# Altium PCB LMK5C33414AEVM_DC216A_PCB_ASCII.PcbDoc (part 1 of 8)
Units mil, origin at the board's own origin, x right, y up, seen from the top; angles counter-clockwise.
Board outline 7000 x 9161 mil, 8 copper layers (L1-Top Layer (GTL), L2-GND Plane (GP1), L3-Mid-Layer 2 (G1), L4-Mid-Layer 3 (G2), L5-Mid-Layer 4 (G3), L6-Mid-Layer 5 (G4), L7-Mid-Layer 6 (G5), L8-Bottom Layer (GBL)), stack 61.2 mil thick; 523 components, 286 nets, 1391 pads, 2227 vias.
Unrouted connection lines stored in the file: 56.
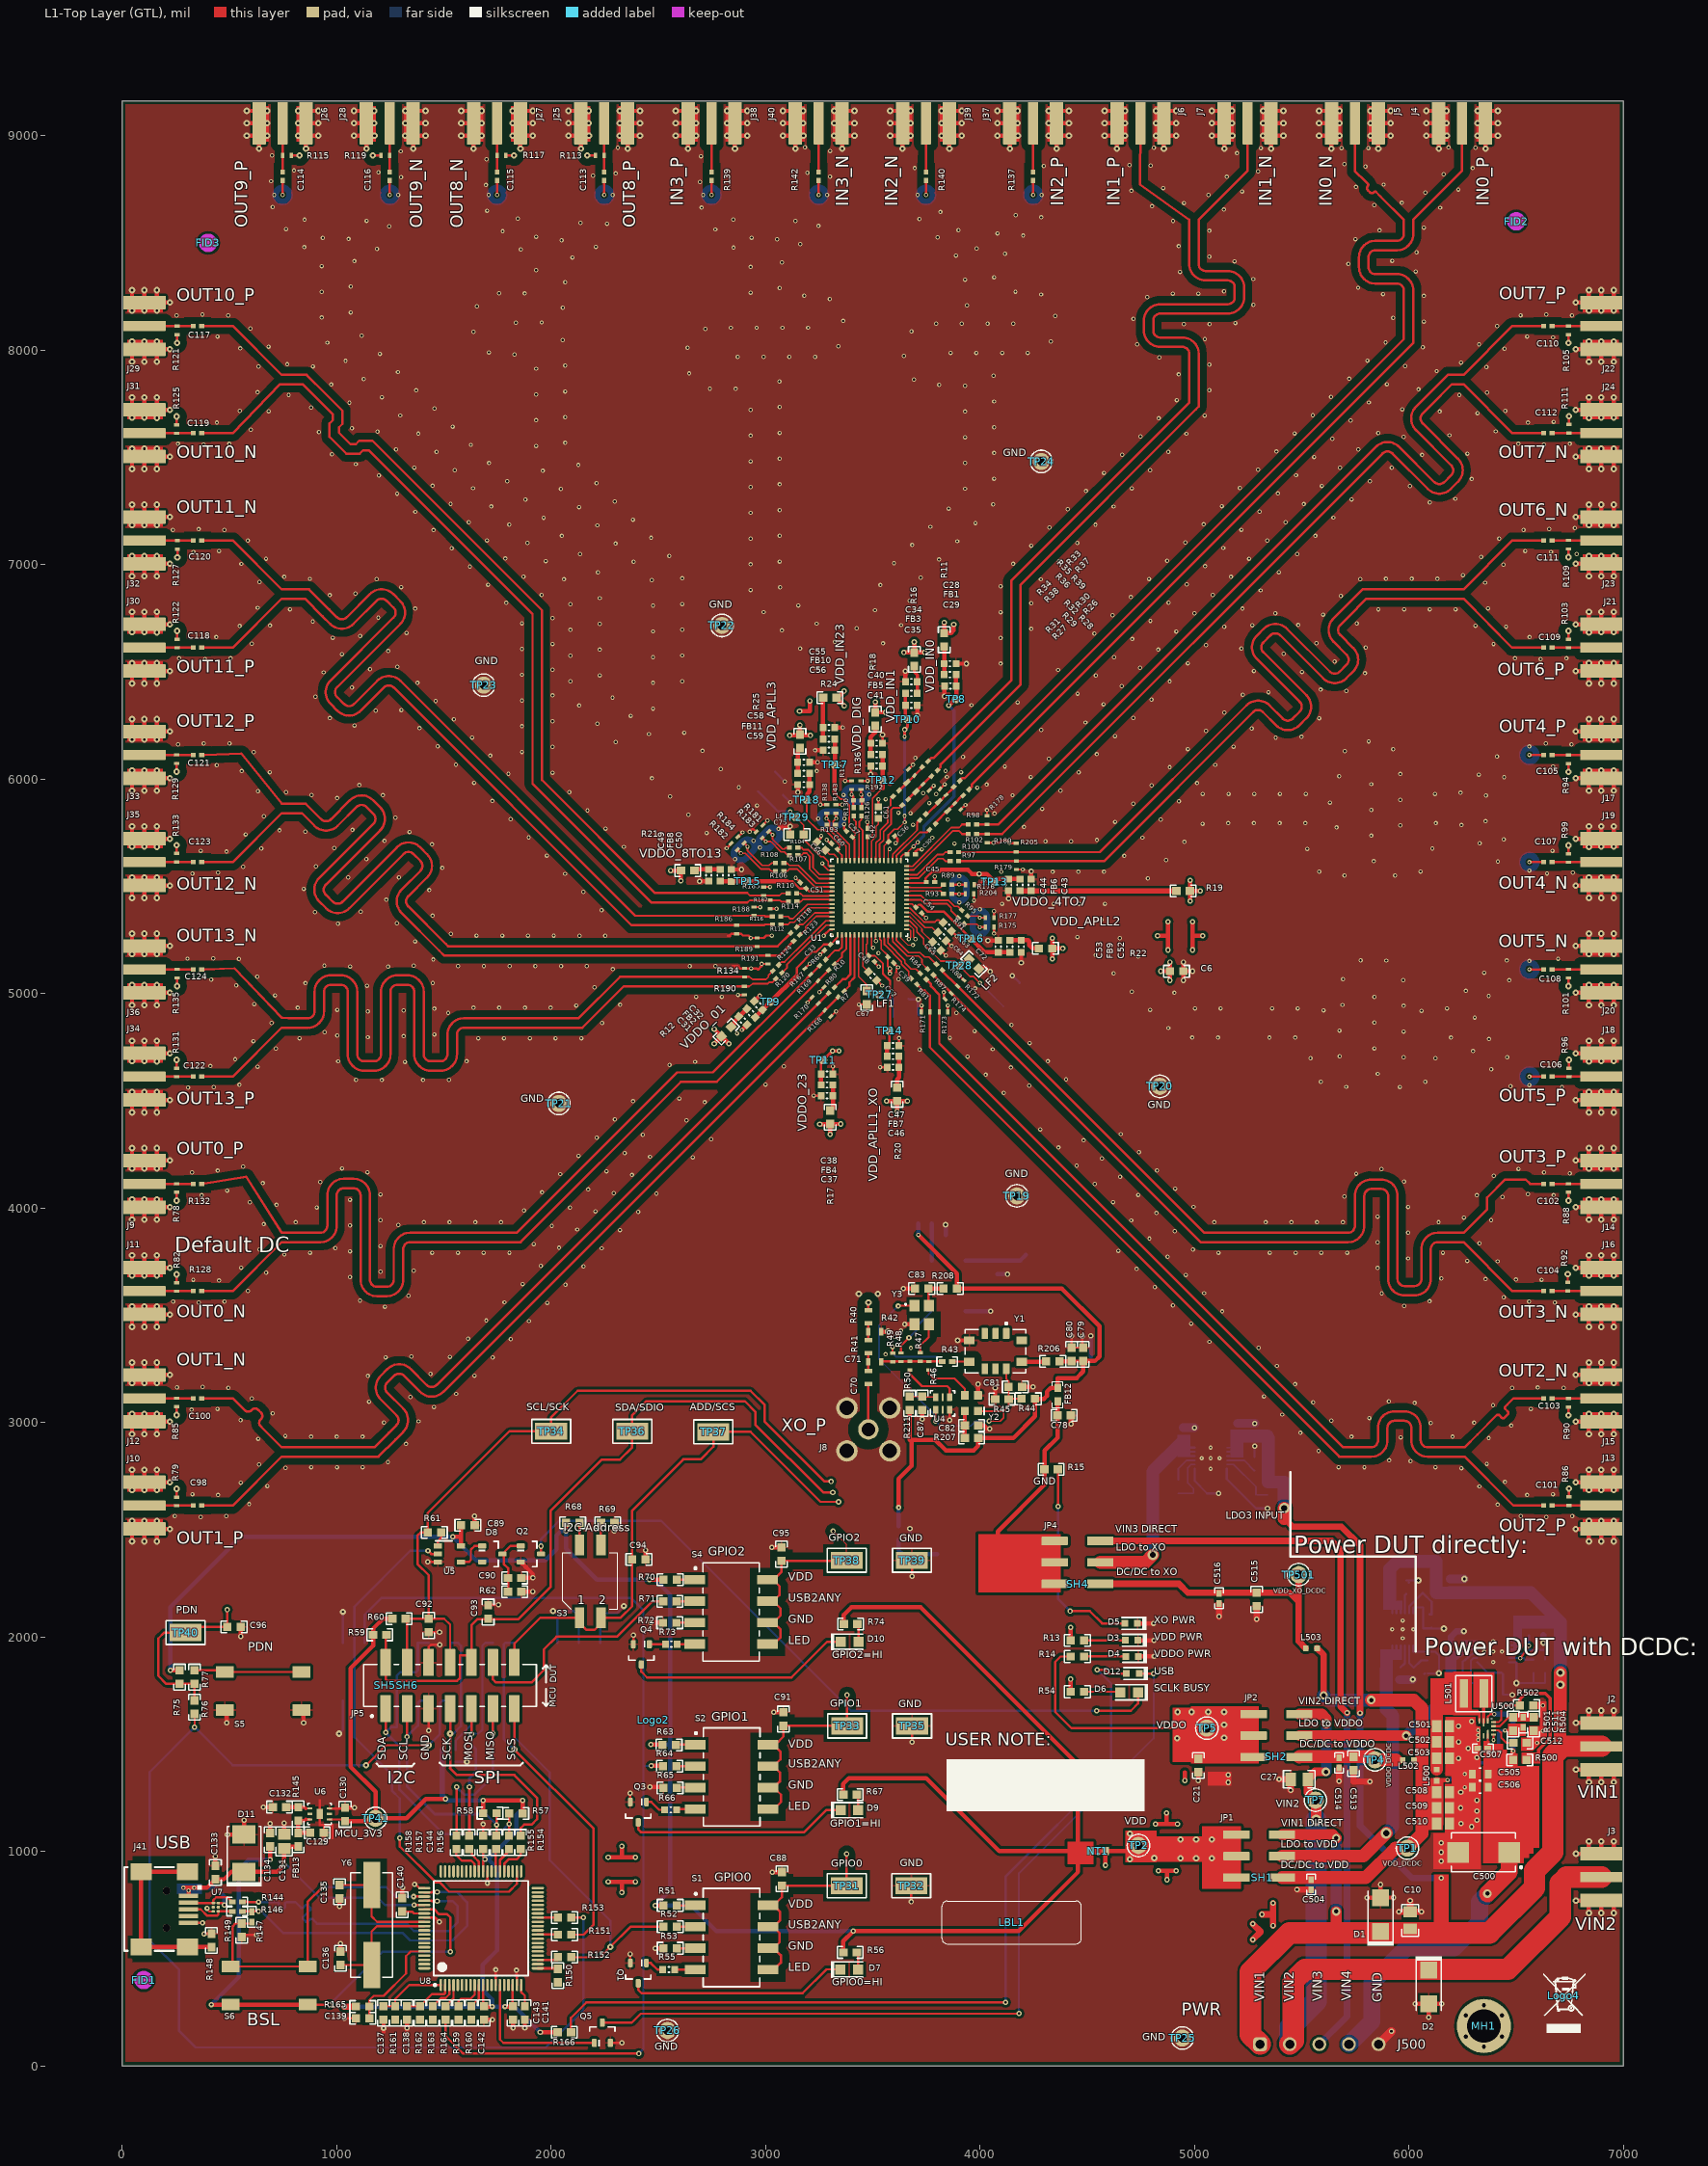
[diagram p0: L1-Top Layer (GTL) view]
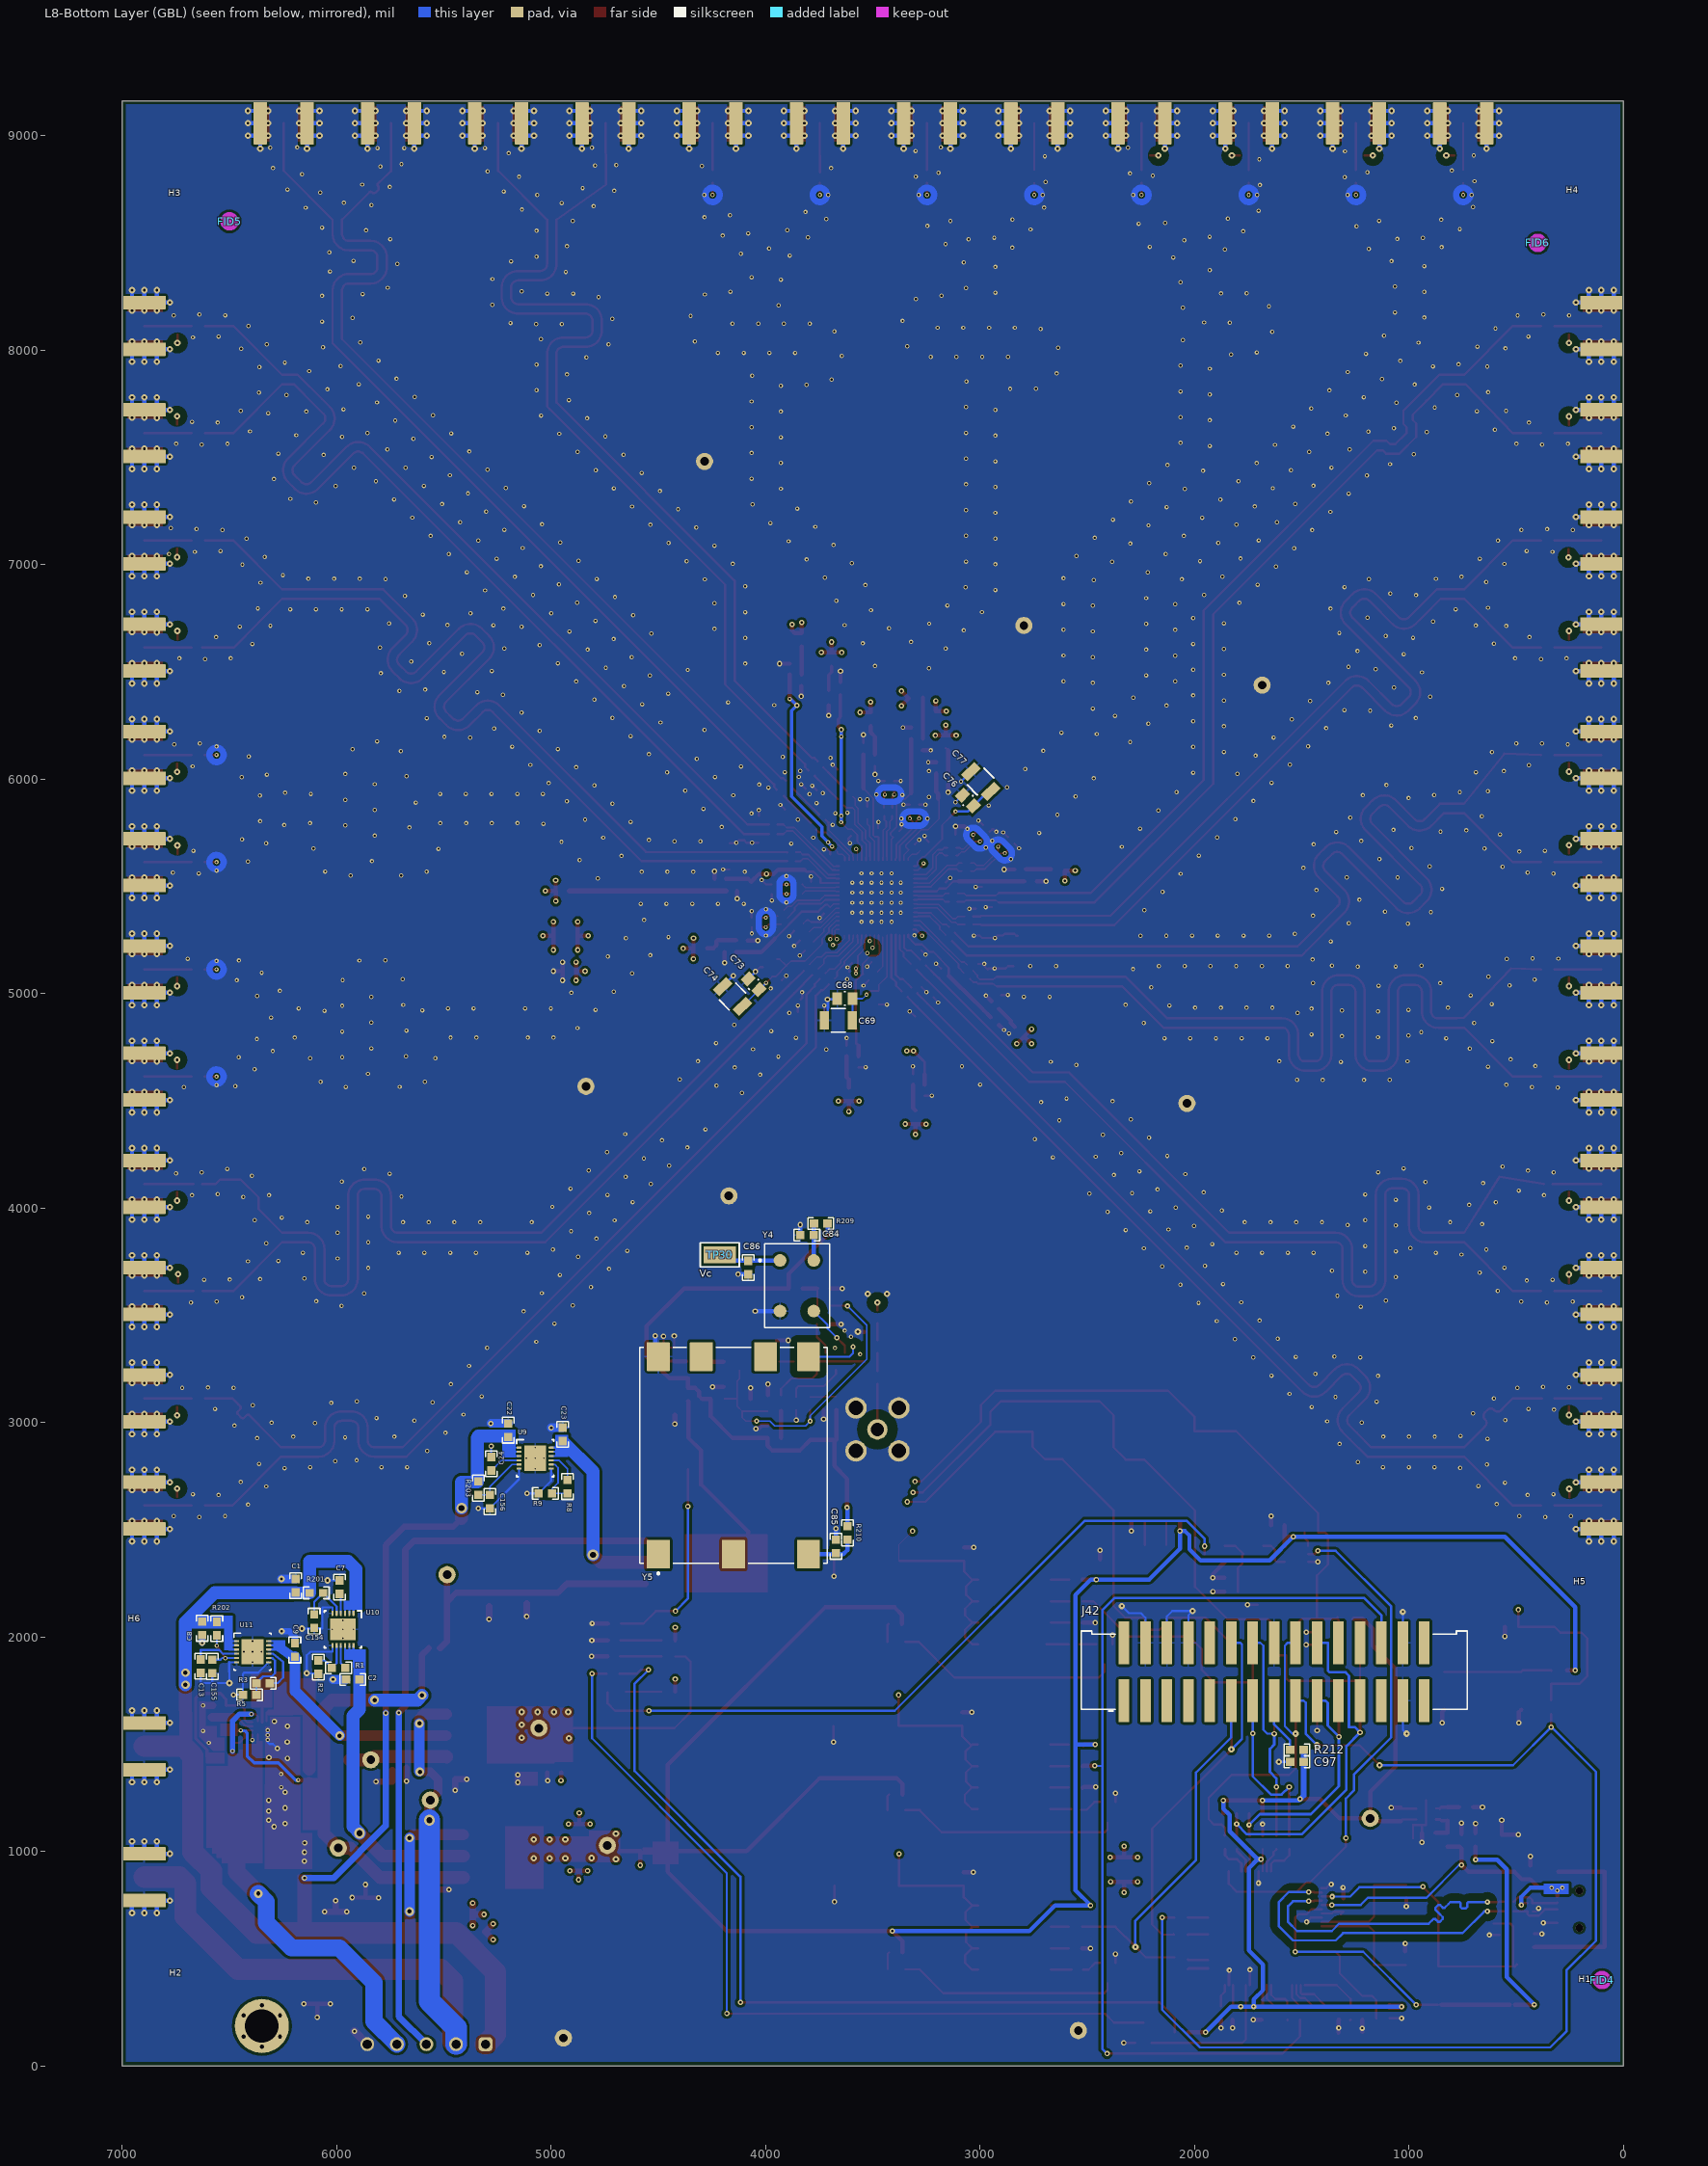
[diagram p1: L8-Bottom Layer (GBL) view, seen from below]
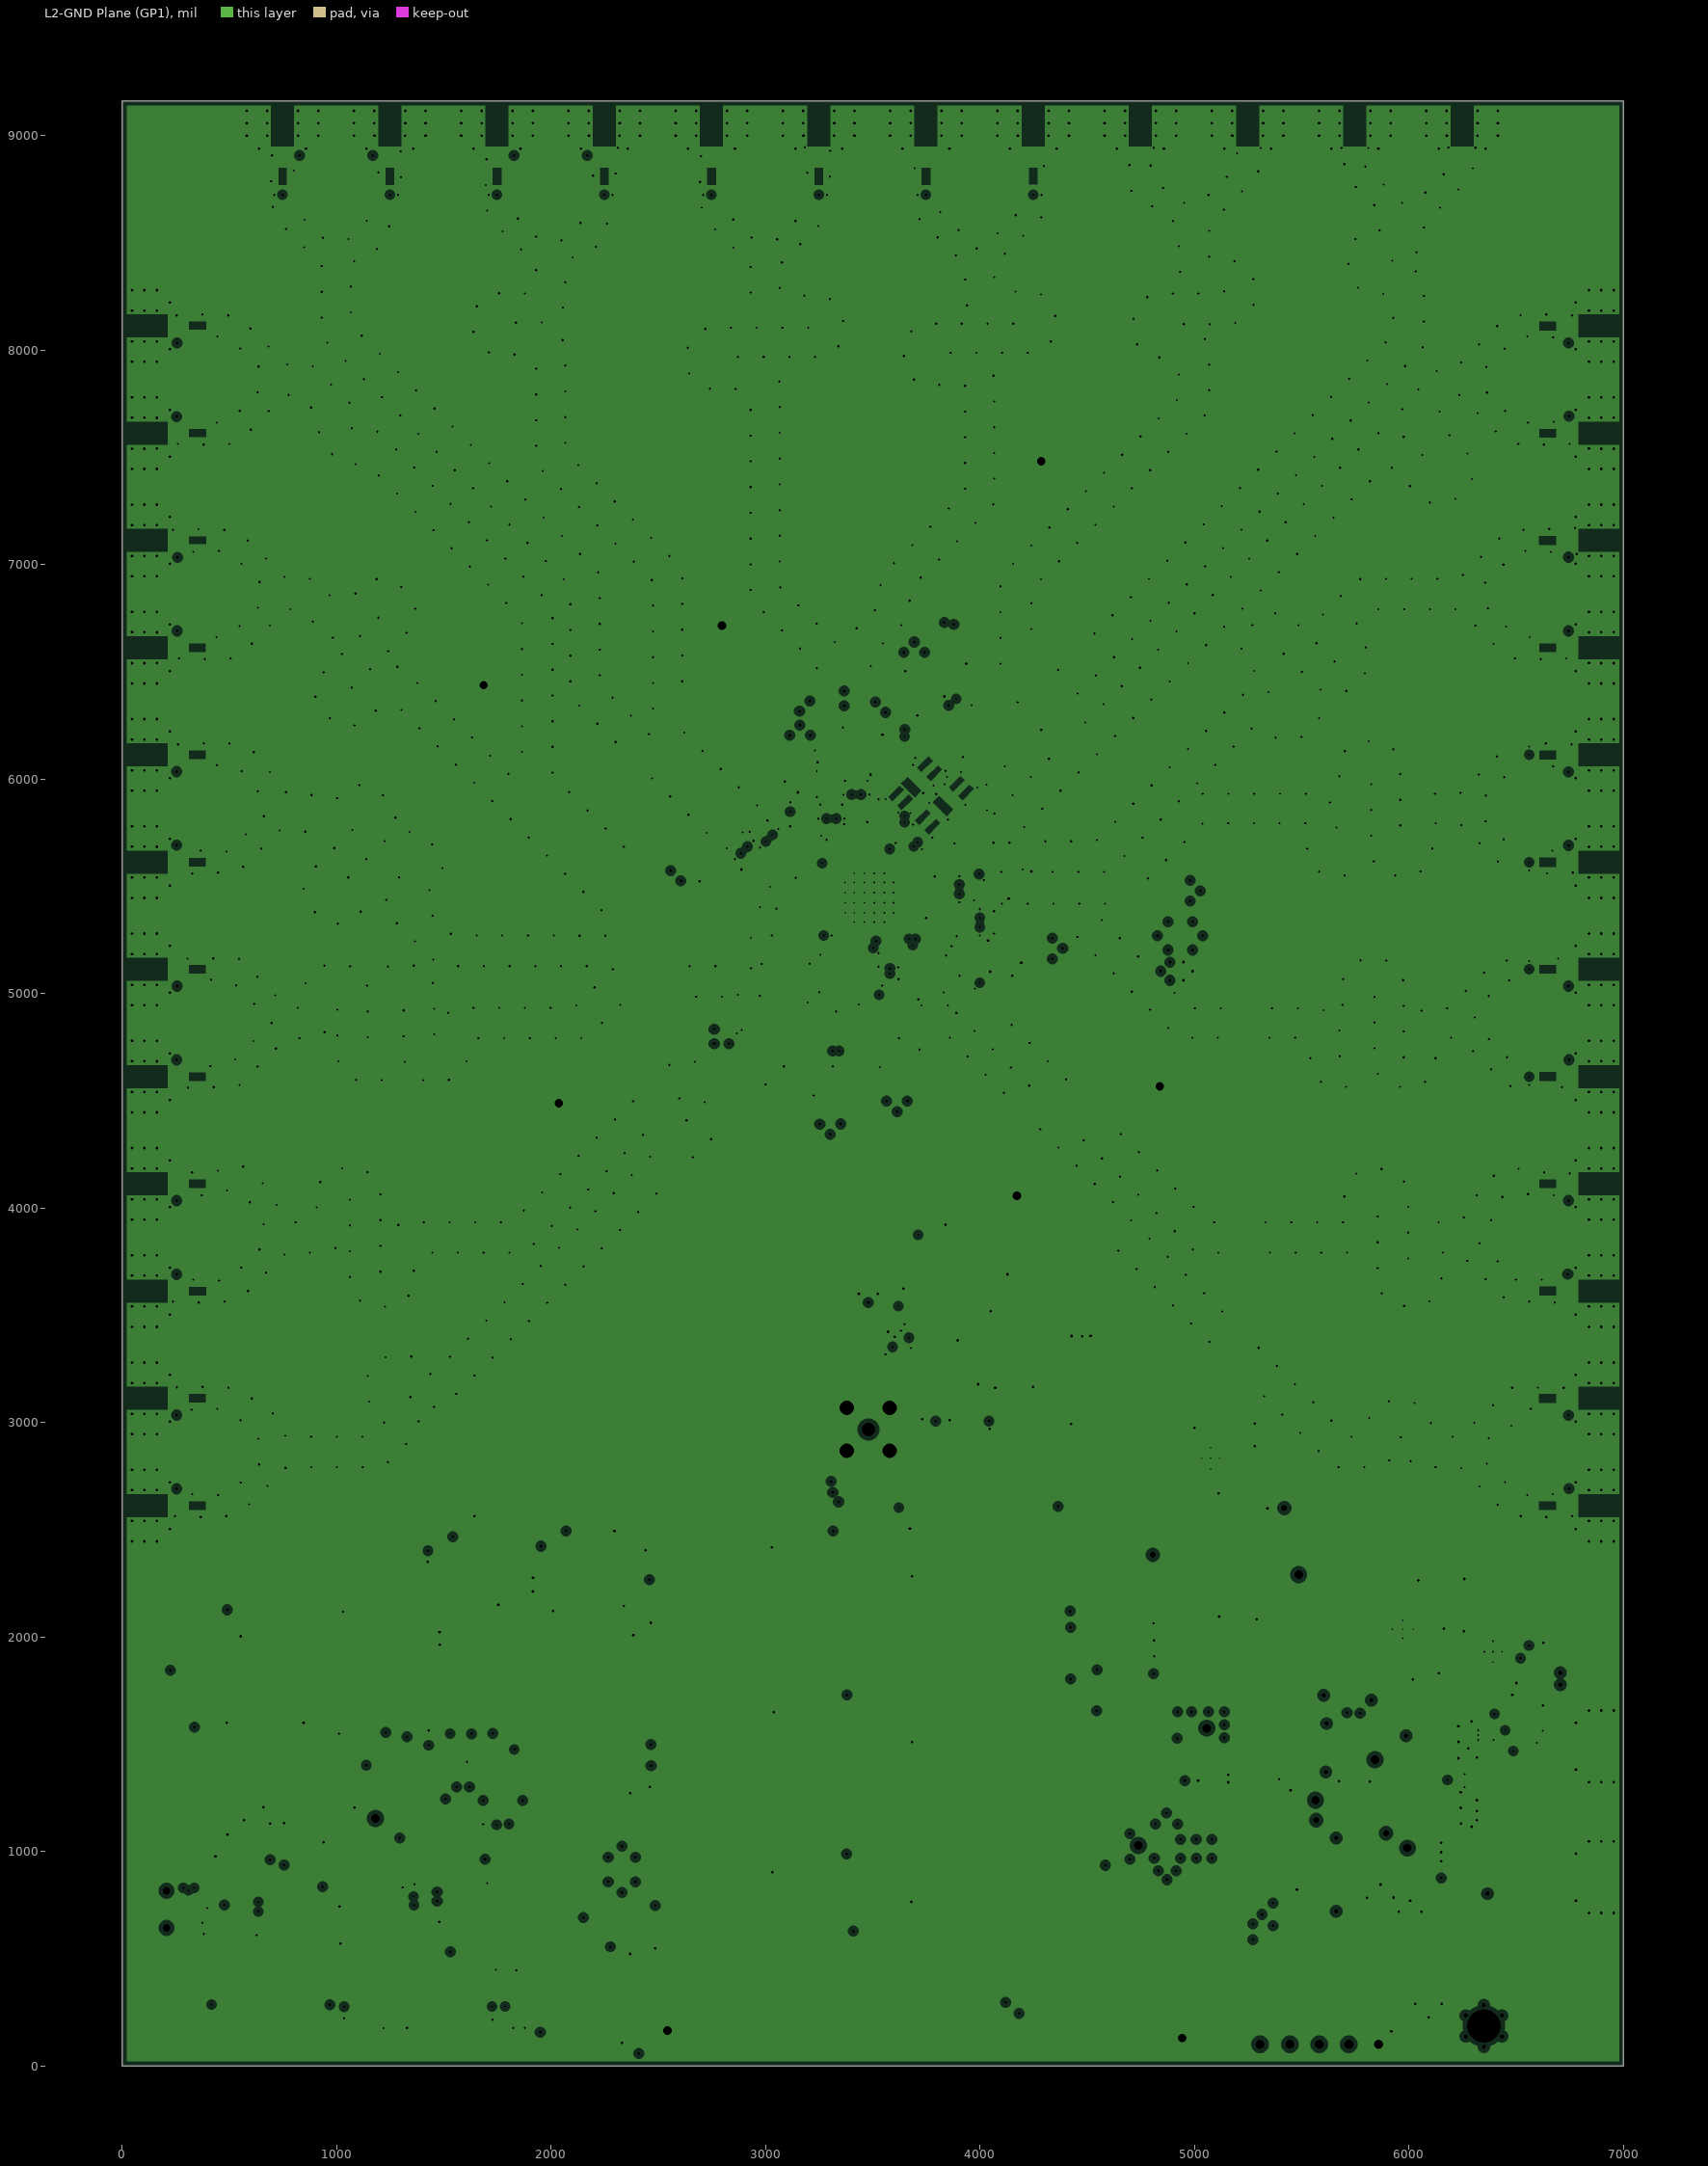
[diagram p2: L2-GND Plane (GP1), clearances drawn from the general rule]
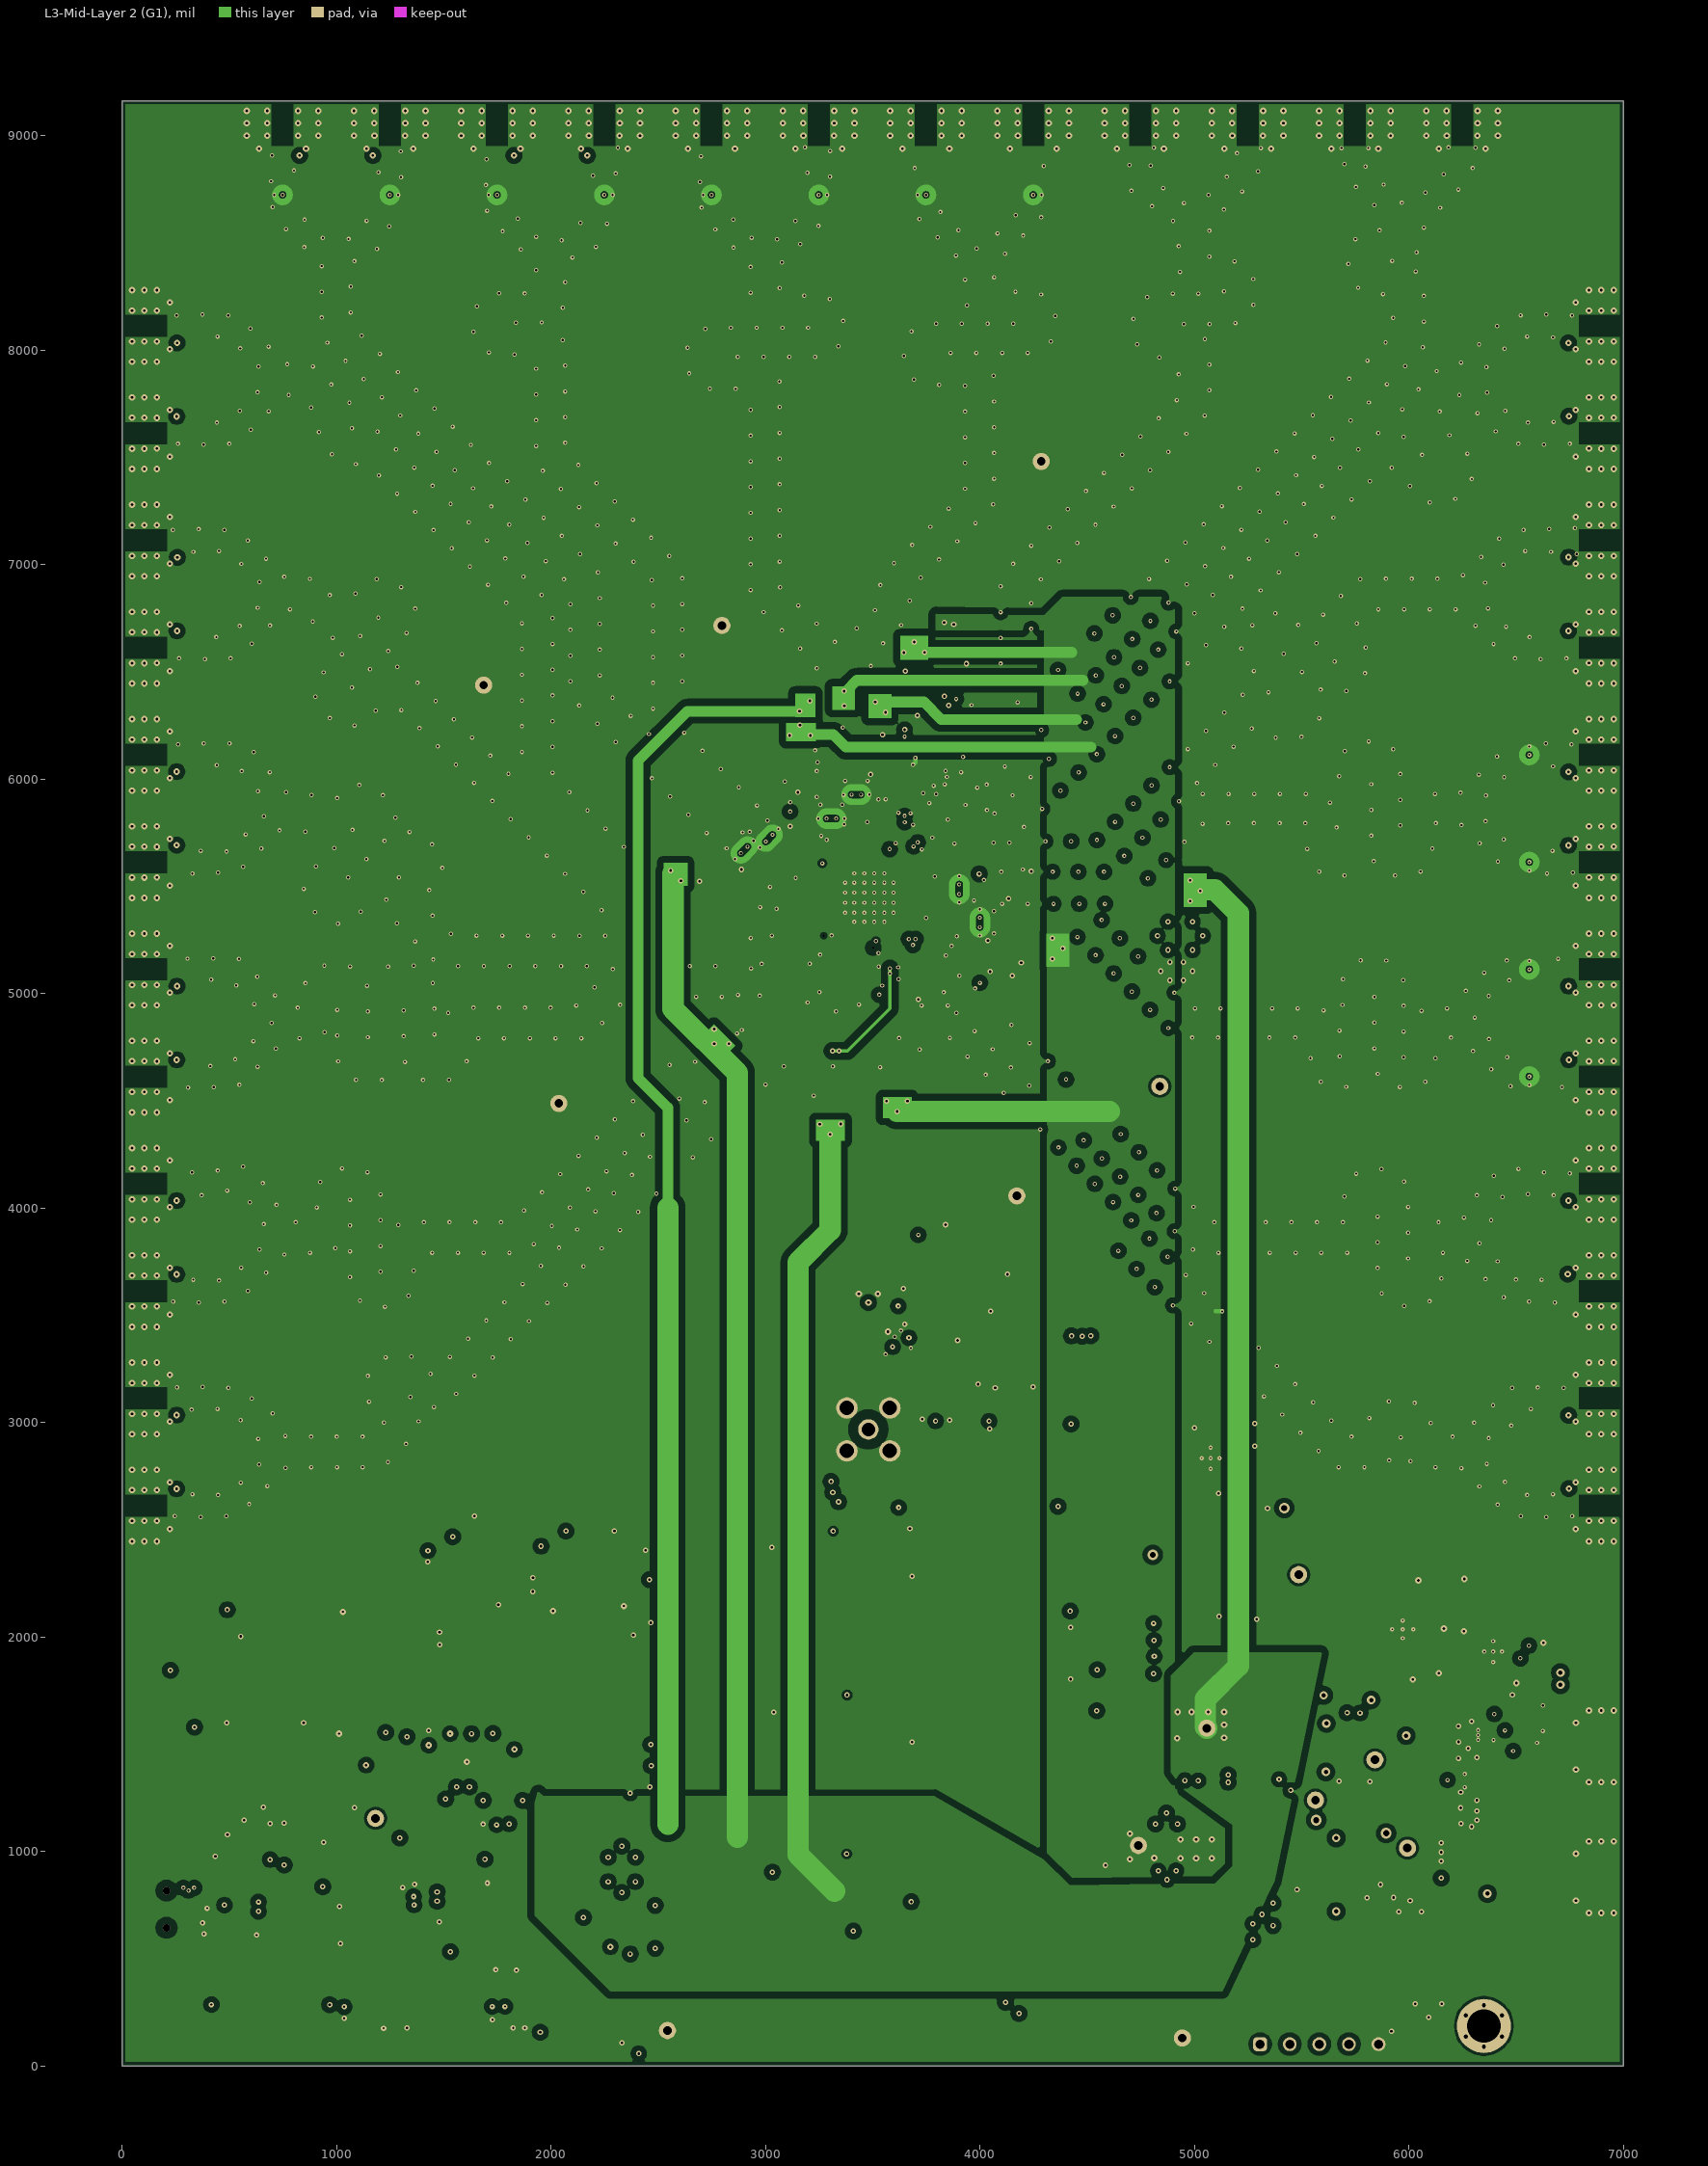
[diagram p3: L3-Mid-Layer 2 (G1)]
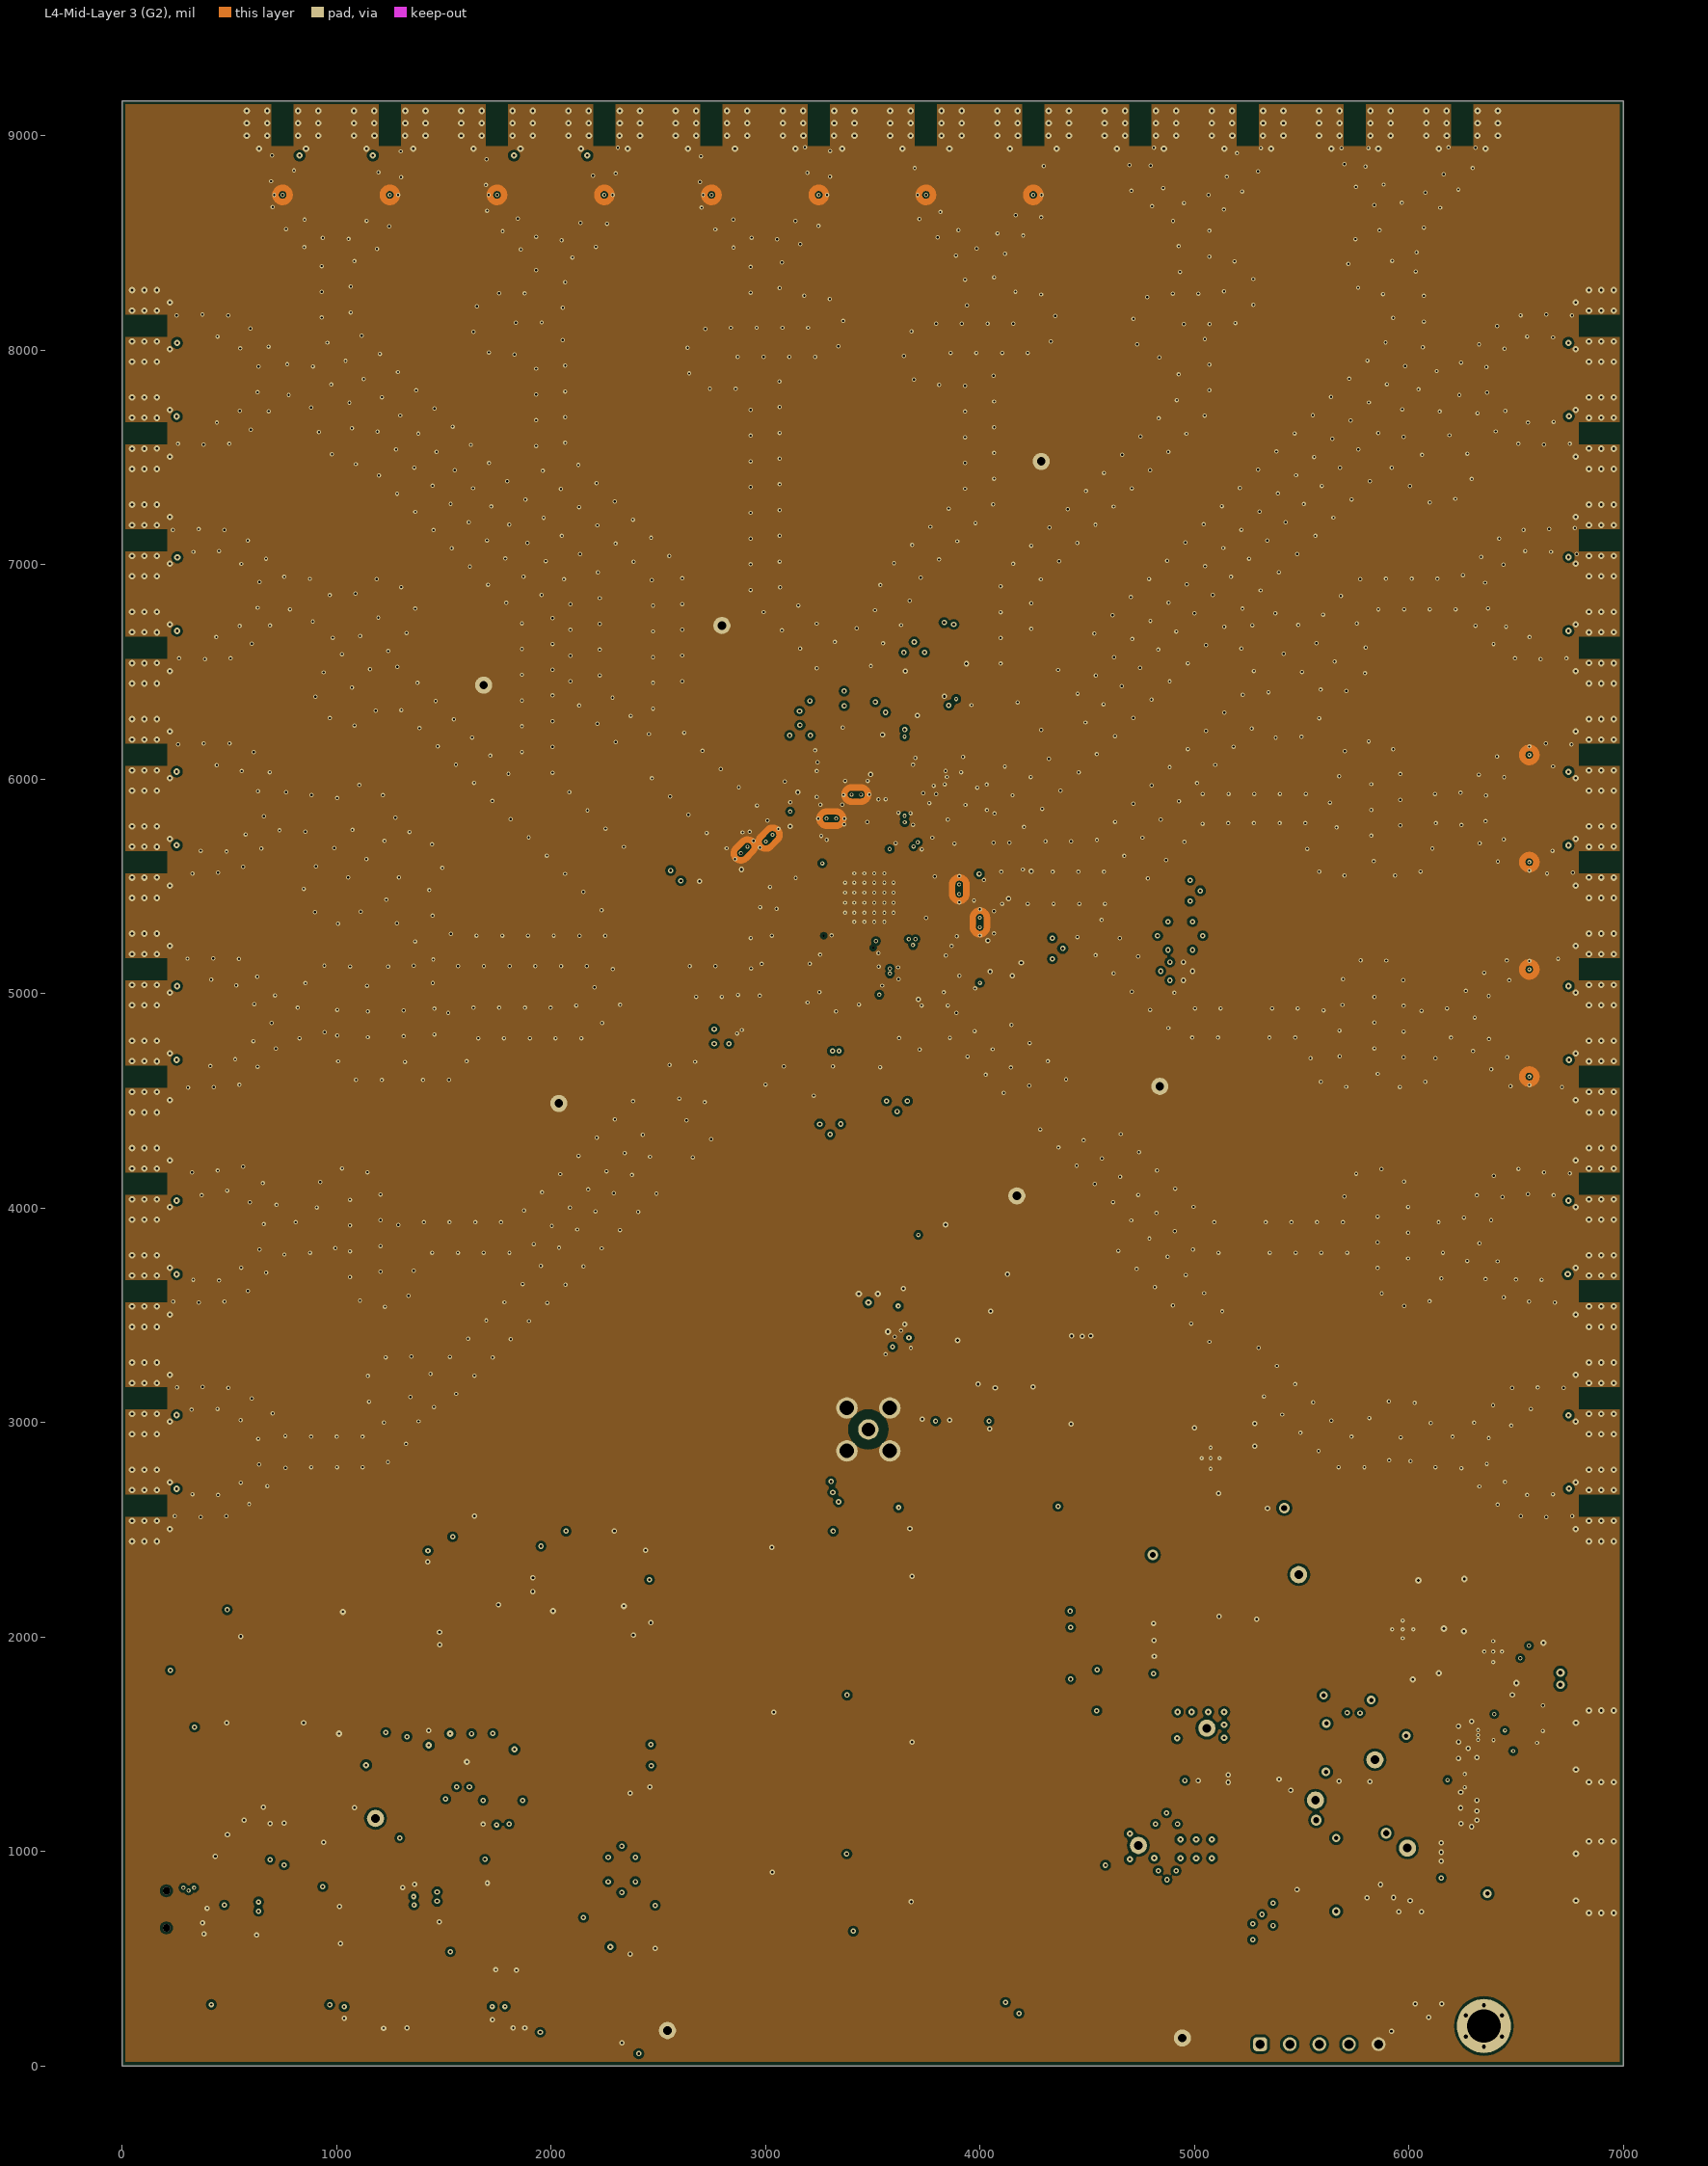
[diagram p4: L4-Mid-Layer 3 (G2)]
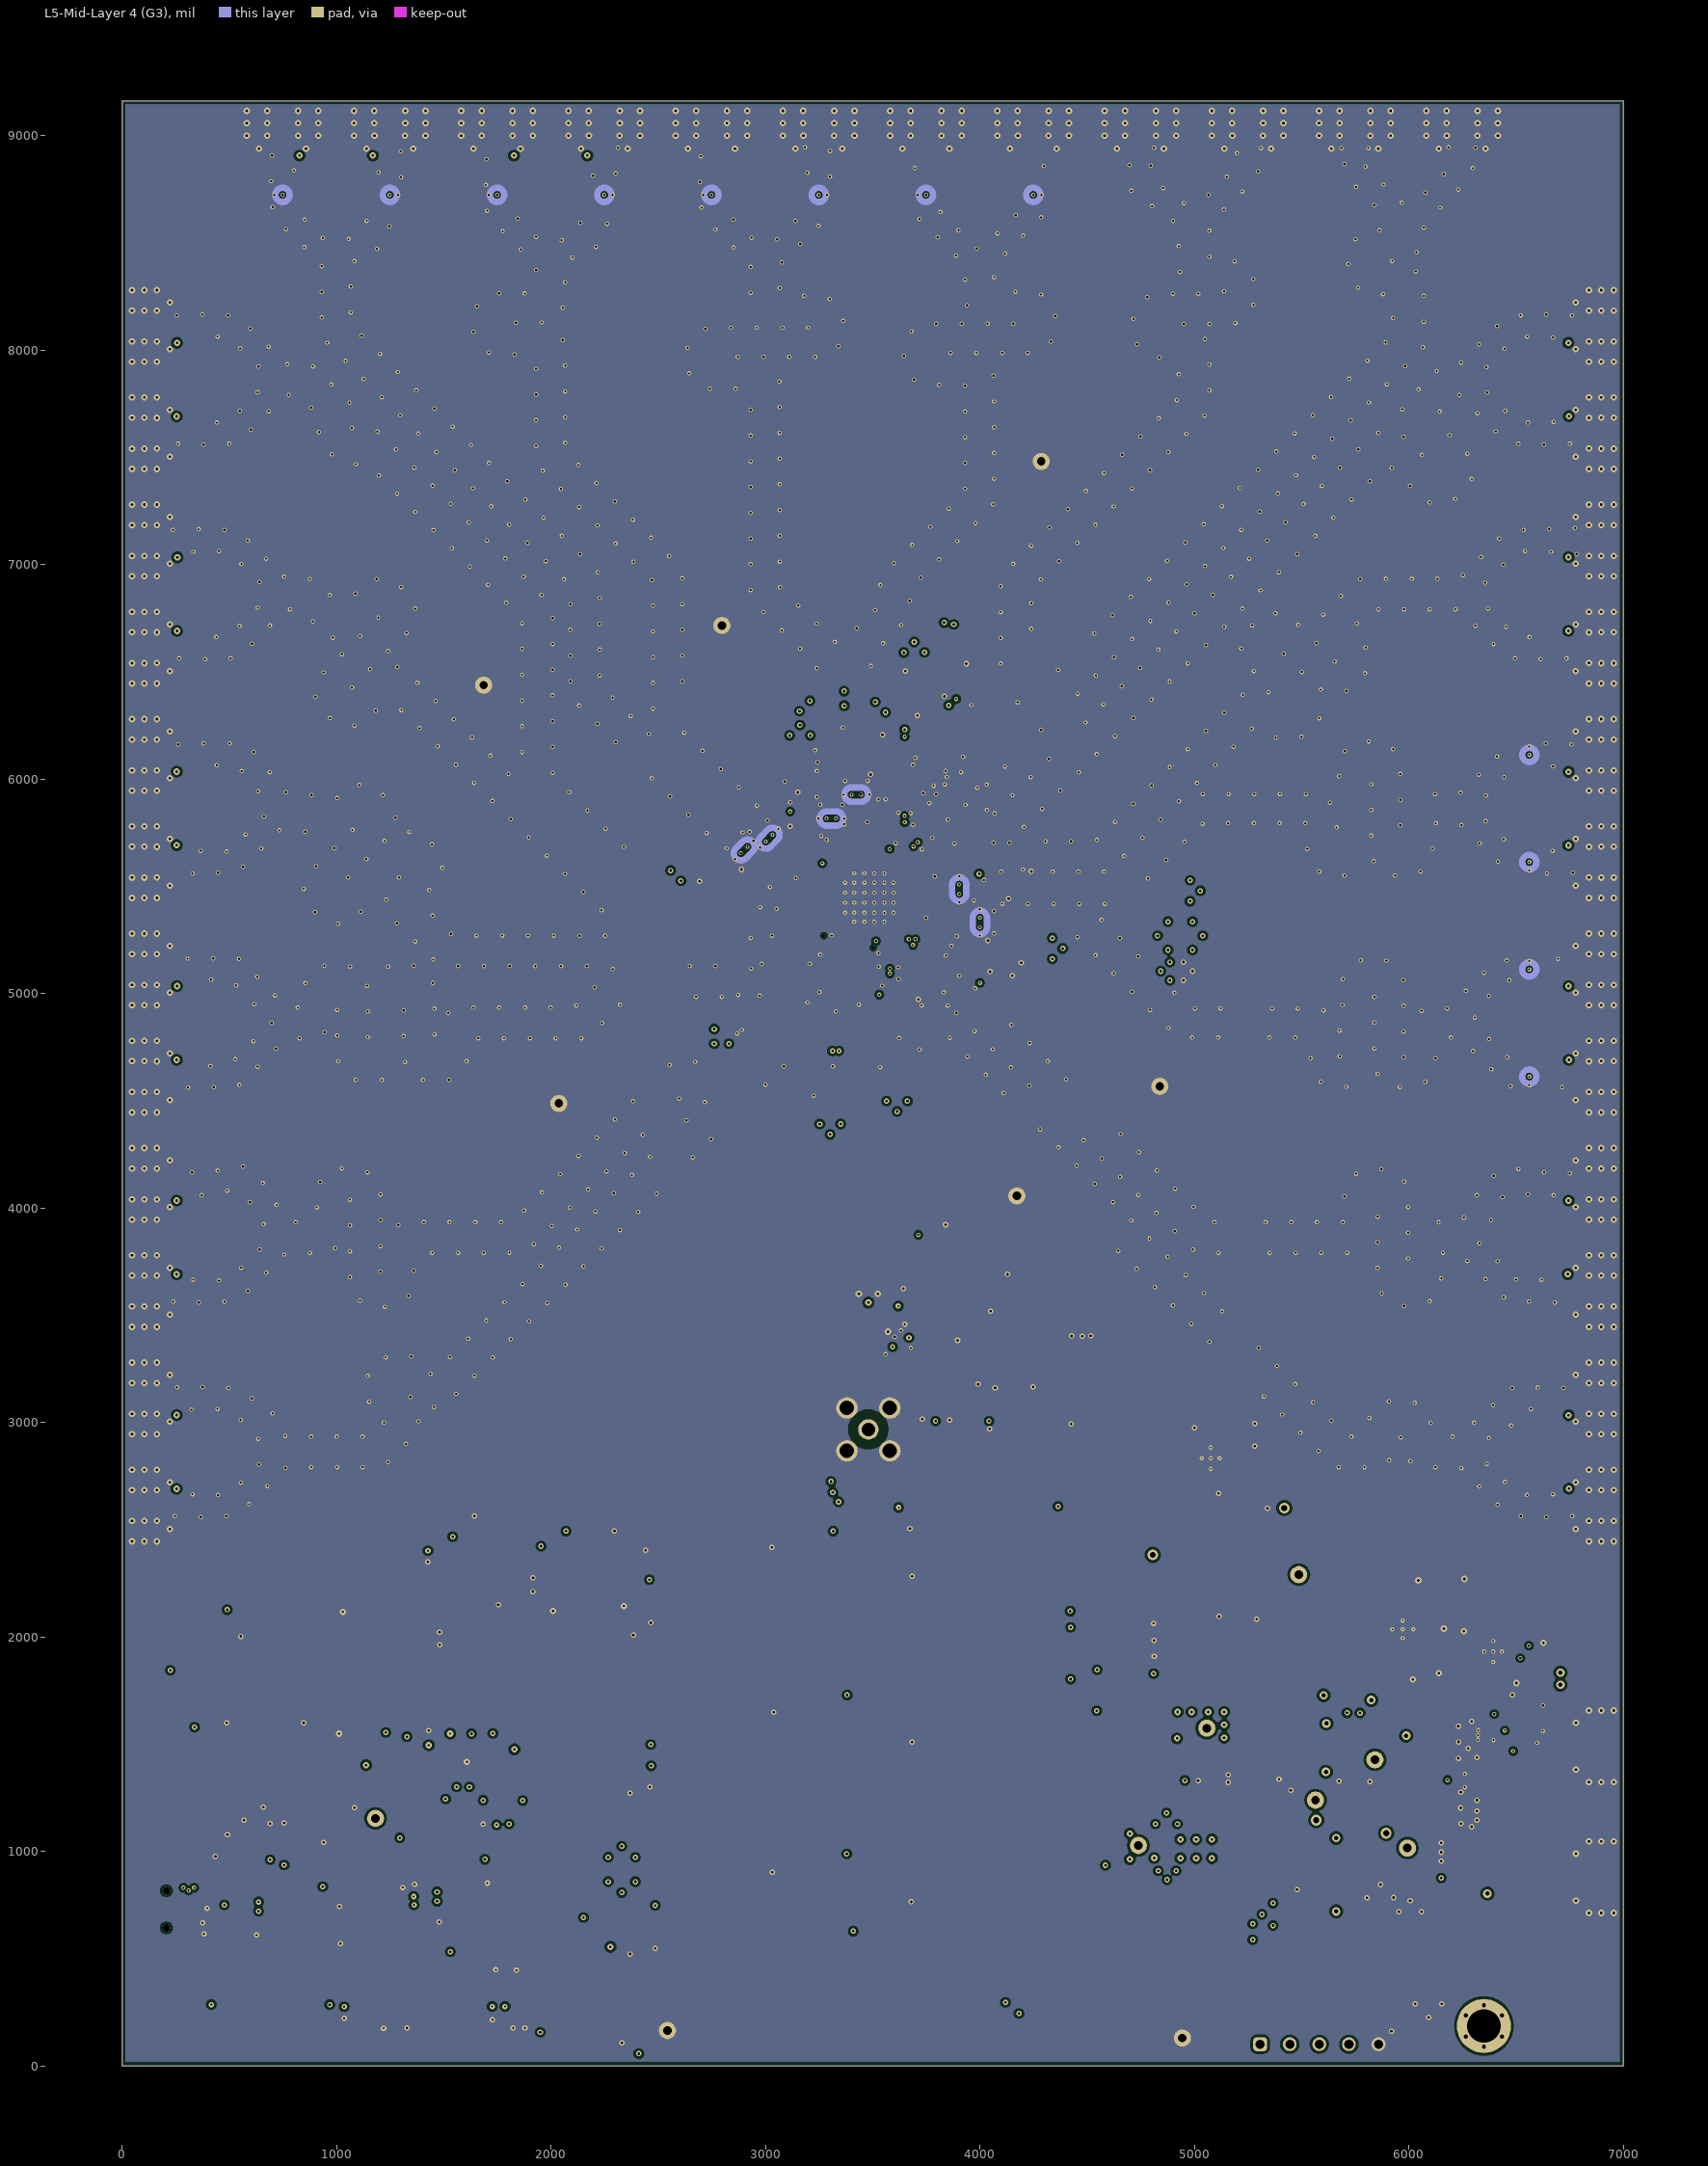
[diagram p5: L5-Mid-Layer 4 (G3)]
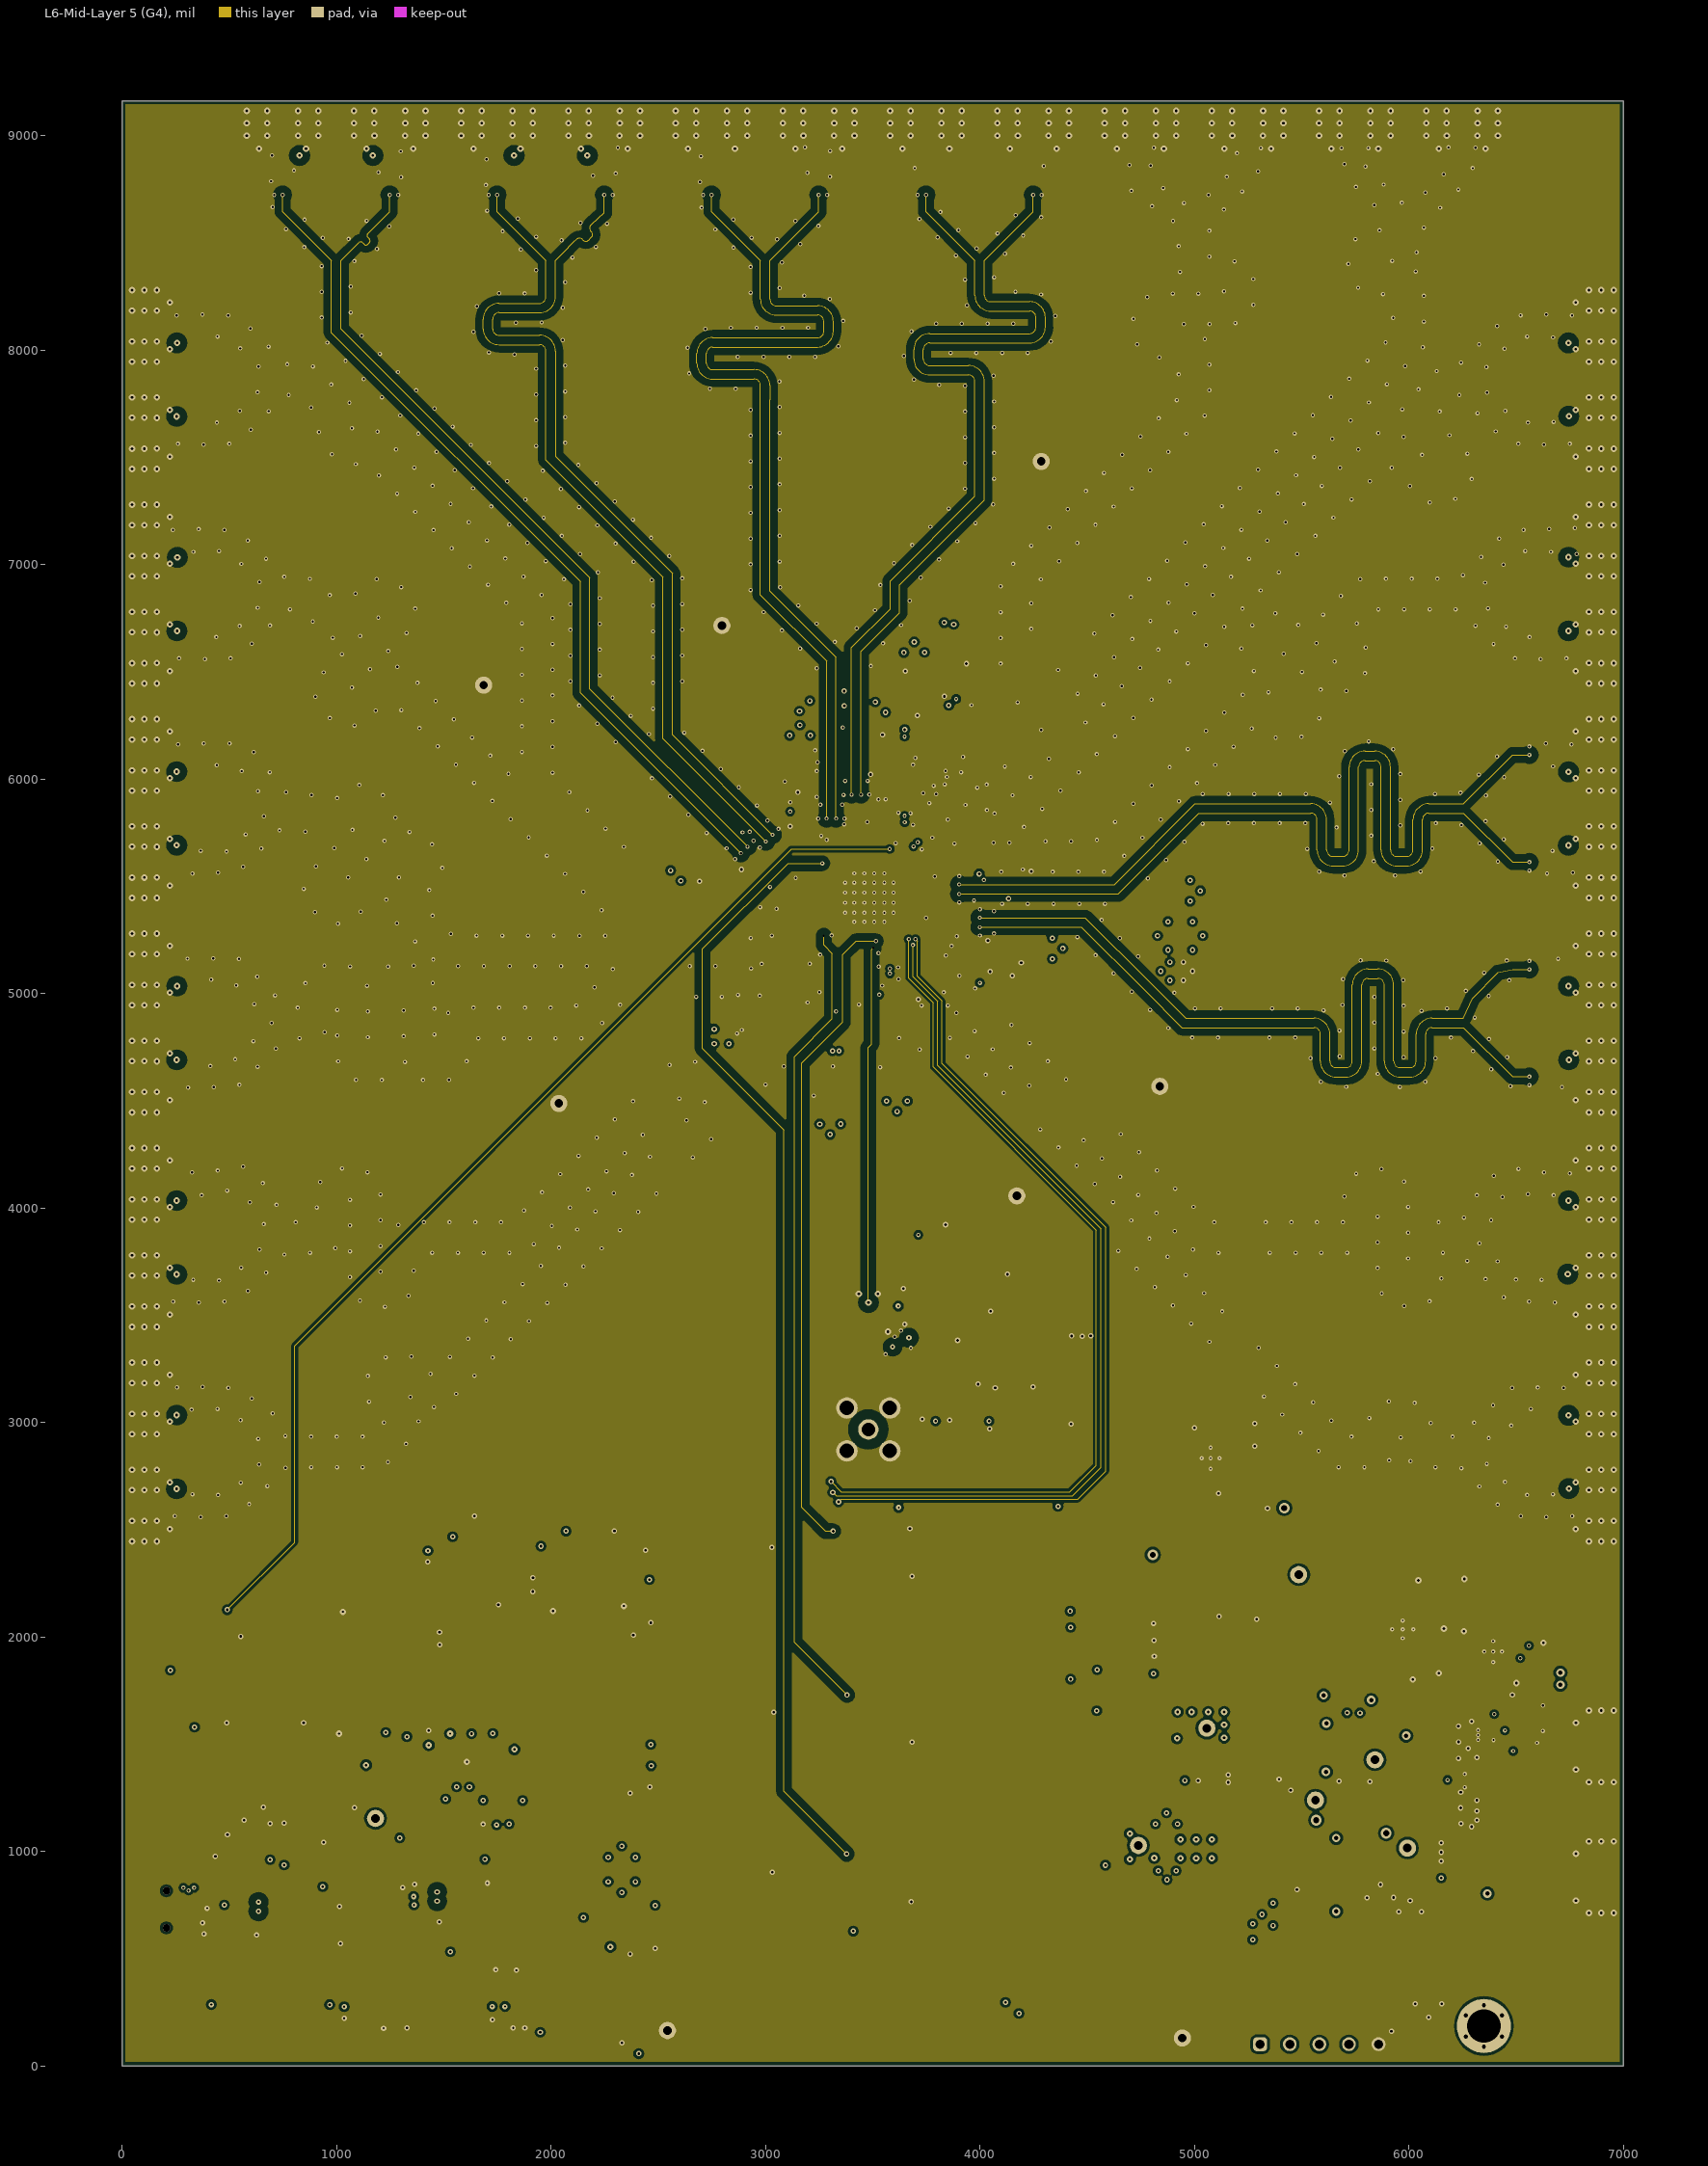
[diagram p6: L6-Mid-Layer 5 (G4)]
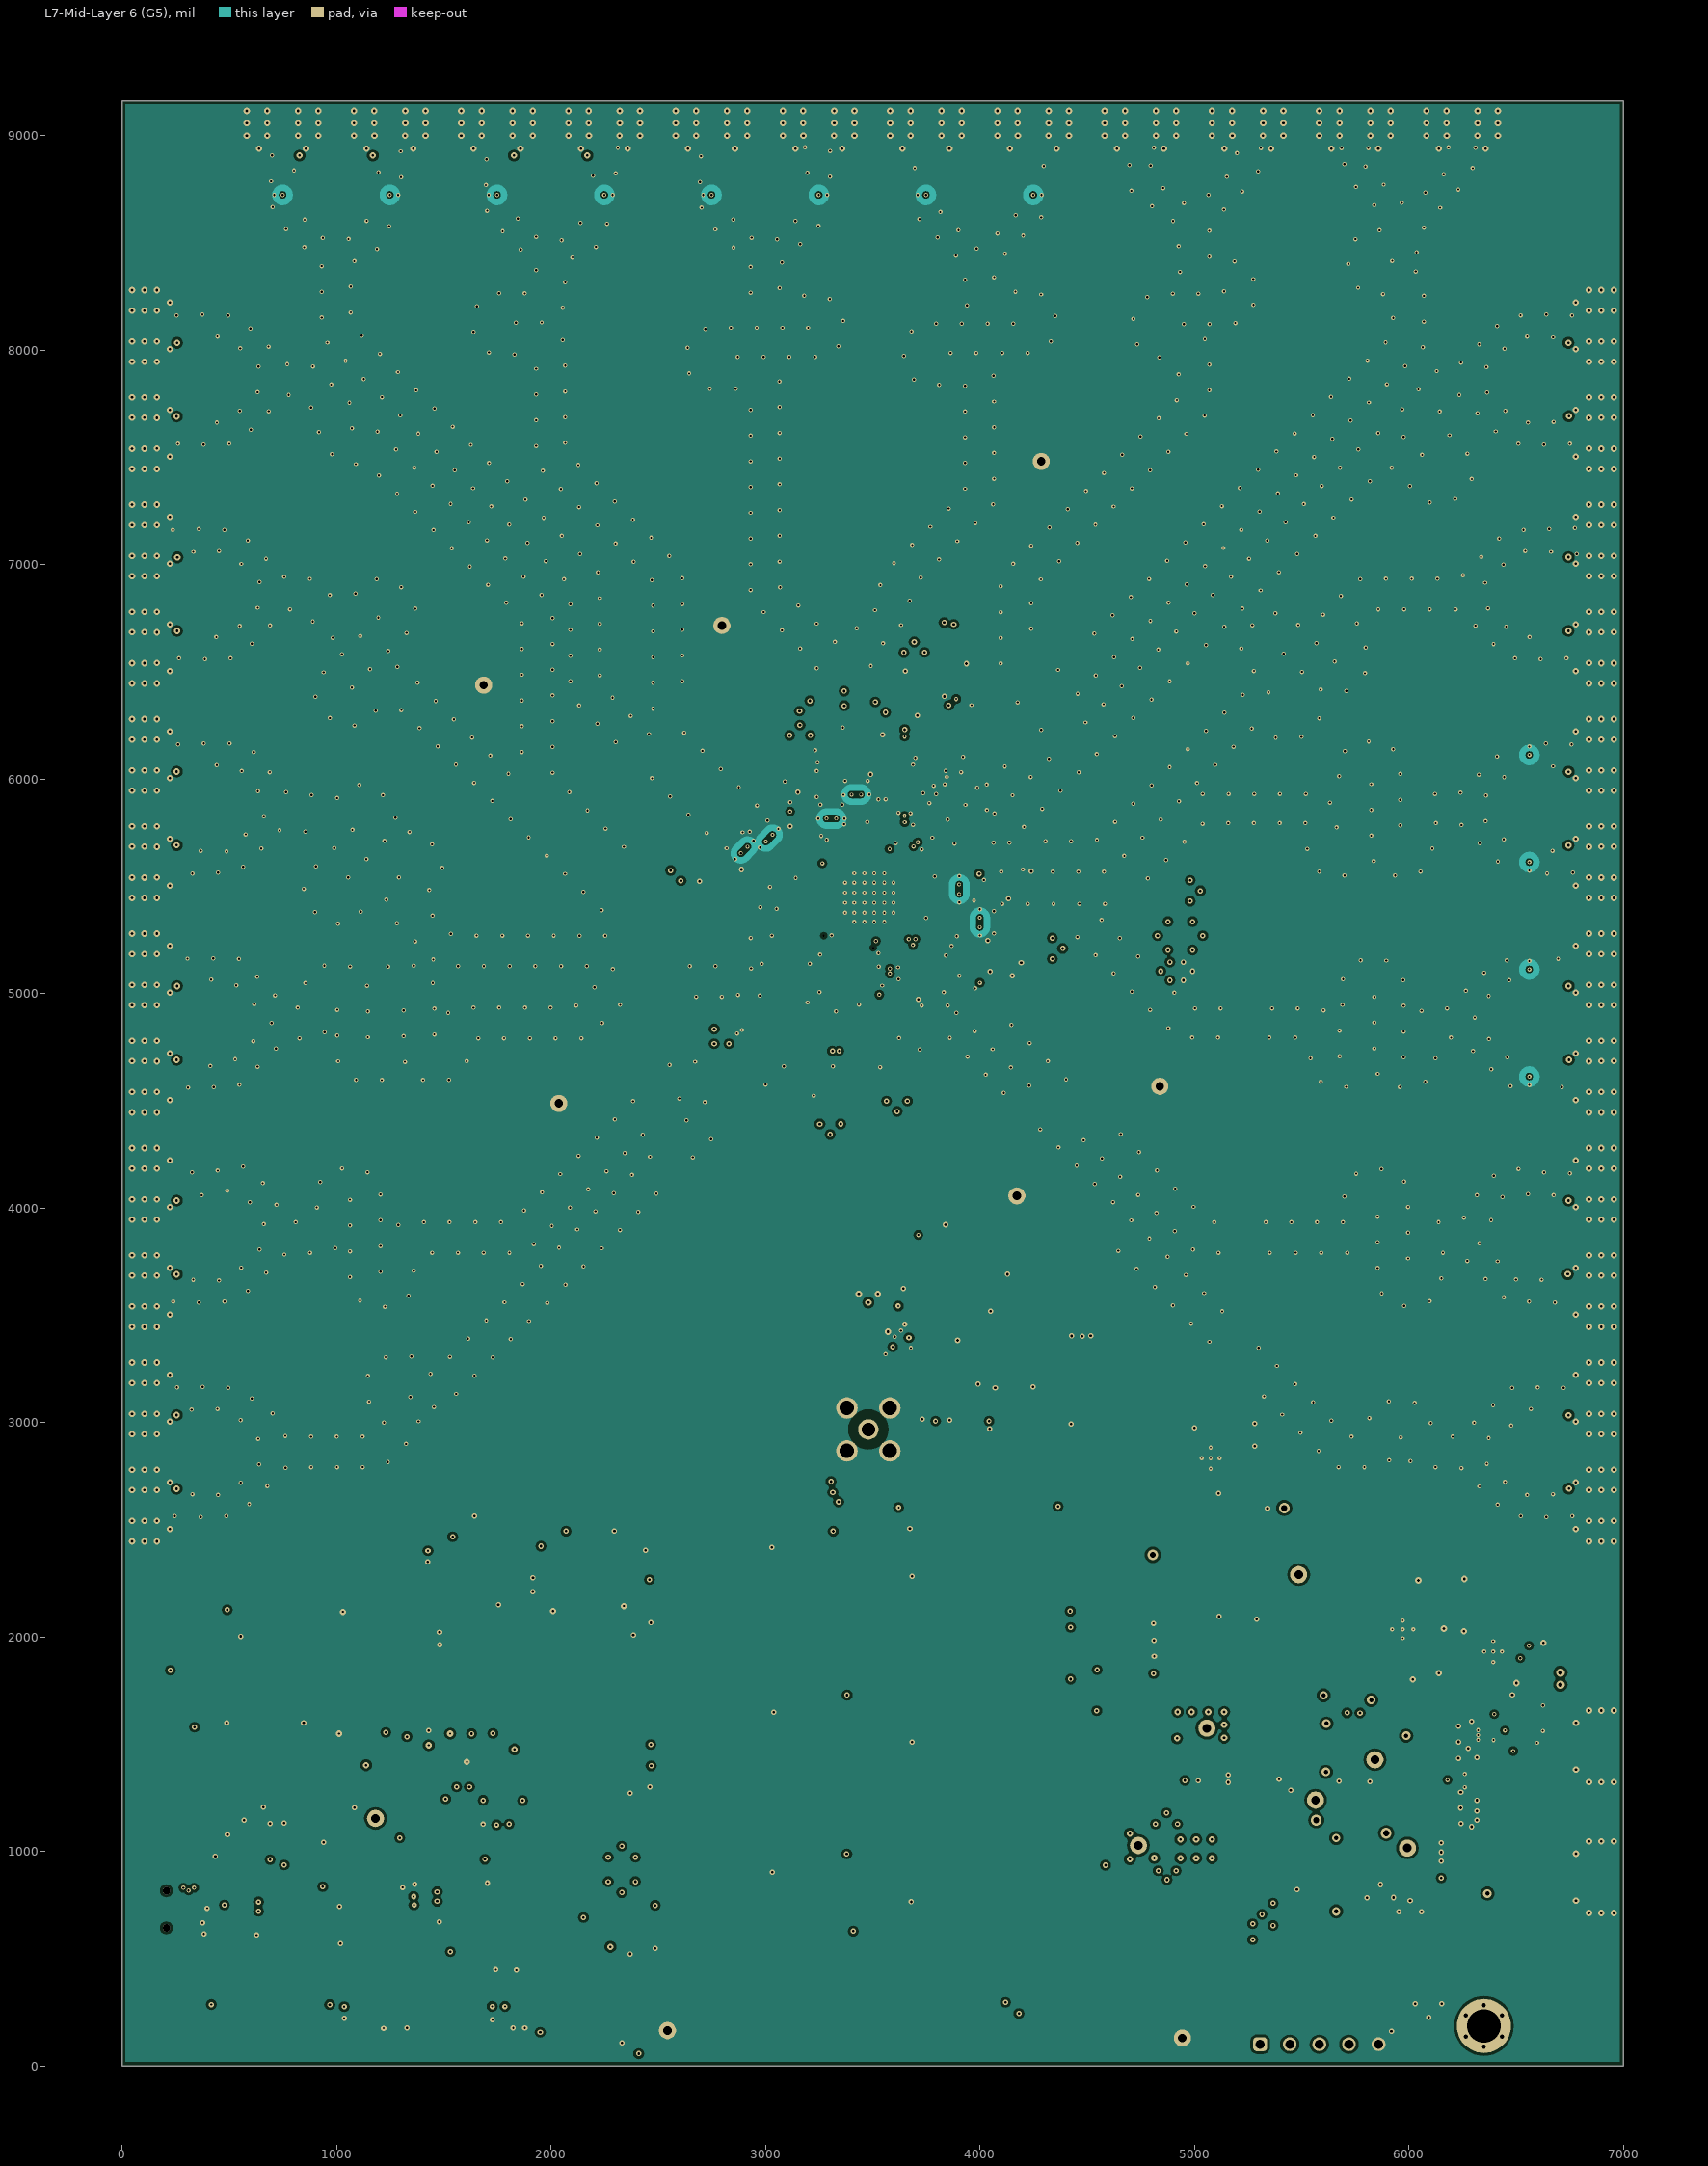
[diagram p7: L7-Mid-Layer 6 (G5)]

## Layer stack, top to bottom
Top Solder: solder mask 0.4, Solder Resist, Dk 3.5
L1-Top Layer (GTL): signal copper 1.4
Dielectric1: core 7, FR-4, Dk 4.6
L2-GND Plane (GP1): plane copper 1.4, net GND
Dielectric2: prepreg 7, FR-4, Dk 4.6
L3-Mid-Layer 2 (G1): signal copper 1.4
Dielectric3: core 5, FR-4, Dk 4.6
L4-Mid-Layer 3 (G2): signal copper 1.4
Dielectric4: prepreg 12, FR-4, Dk 4.6
L5-Mid-Layer 4 (G3): signal copper 1.4
Dielectric5: core 5, FR-4, Dk 4.6
L6-Mid-Layer 5 (G4): signal copper 1.4
Dielectric6: prepreg 7, FR-4, Dk 4.6
L7-Mid-Layer 6 (G5): signal copper 1.4
Dielectric7: core 7, FR-4, Dk 4.6
L8-Bottom Layer (GBL): signal copper 1.4
Bottom Solder: solder mask 0.4, Solder Resist, Dk 3.5

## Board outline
0,0 7000,0 7000,9161 0,9161
cut-out: -692,-2434 -682,-2434 -682,-2424 -692,-2424

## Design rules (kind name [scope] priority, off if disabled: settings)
AcuteAngle [All] p1: minimum=4.50000000000000E+0001 checktracksonly=FALSE
AssemblyTestPointUsage [All] p1: valid=2
BoardOutlineClearance BoardOutlineClearance_MountingHoles [OnCopper and InComponentClass('Mounting Holes')] p1: gap=40 ignorepadtopadclearanceinfootprint=FALSE
BoardOutlineClearance BoardOutlineClearance_Poly [OnCopper and InPoly] p2: gap=15 ignorepadtopadclearanceinfootprint=FALSE
BoardOutlineClearance [OnCopper and Not InComponentClass('Logo') and not InComponentClass('FiducialMark') and not InRegion(1000,500,4000,800)] p3: gap=5 ignorepadtopadclearanceinfootprint=FALSE
BoardOutlineClearance BoardOutlineClearance_1 [OnCopper and Not InComponentClass('Logo') and not InComponentClass('FiducialMark')] p4 off: gap=5 ignorepadtopadclearanceinfootprint=FALSE
Clearance Clearance_SMA_XO_N [InPolygon vs InNet('SMA_XO_N')] p1: gap=33 ignorepadtopadclearanceinfootprint=FALSE except(0: Arc-Hole Track-Hole SMDPad-Hole THPad-Hole Via-Hole Fill-Hole Poly-Hole Region-Hole Text-Hole; 12: Track-Track SMDPad-SMDPad Via-Poly; 46: THPad-Poly)
Clearance Clearance_SMA_XO_P [InPolygon vs InNet('SMA_XO_P')] p2: gap=33 ignorepadtopadclearanceinfootprint=FALSE except(0: Arc-Hole Track-Track Track-Hole SMDPad-Hole THPad-Hole Via-Hole Fill-Hole Poly-Hole Region-Hole Text-Hole; 12: SMDPad-SMDPad Via-Poly; 46: THPad-Poly THPad-Region)
Clearance Clearance_INSEL1_0 [InPolygon vs InNet('INSEL1_0')] p3: gap=33 ignorepadtopadclearanceinfootprint=FALSE except(0: Arc-Hole Track-Track Track-Hole SMDPad-Hole THPad-Hole Via-Hole Fill-Hole Poly-Hole Region-Hole Text-Hole; 12: SMDPad-SMDPad Via-Poly; 26.5: THPad-Poly THPad-Region)
Clearance Clearance_INSEL0_1 [InPolygon vs InNet('INSEL0_1')] p4: gap=33 ignorepadtopadclearanceinfootprint=FALSE except(0: Arc-Hole Track-Track Track-Hole SMDPad-Hole THPad-Hole Via-Hole Fill-Hole Poly-Hole Region-Hole Text-Hole; 12: SMDPad-SMDPad Via-Poly; 26.5: THPad-Poly THPad-Region)
Clearance Clearance_INSEL1_1 [InPolygon vs InNet('INSEL1_1')] p5: gap=33 ignorepadtopadclearanceinfootprint=FALSE except(0: Arc-Hole Track-Track Track-Hole SMDPad-Hole THPad-Hole Via-Hole Fill-Hole Poly-Hole Region-Hole Text-Hole; 12: SMDPad-SMDPad Via-Poly; 26.5: THPad-Poly THPad-Region)
Clearance Clearance_INSEL0_0 [InPolygon vs InNet('INSEL0_0')] p6: gap=33 ignorepadtopadclearanceinfootprint=FALSE except(0: Arc-Hole Track-Track Track-Hole SMDPad-Hole THPad-Hole Via-Hole Fill-Hole Poly-Hole Region-Hole Text-Hole; 12: SMDPad-SMDPad Via-Poly; 26.5: THPad-Poly THPad-Region)
Clearance Clearance_gpio5 [InPolygon vs InNet('LMKGPIO5')] p7: gap=33 ignorepadtopadclearanceinfootprint=FALSE except(0: Arc-Hole Track-Track Track-Hole SMDPad-Hole THPad-Hole Via-Hole Fill-Hole Poly-Hole Region-Hole Text-Hole; 12: SMDPad-SMDPad Via-Poly; 26.5: THPad-Poly THPad-Region)
Clearance Clearance_gpio4 [InPolygon vs InNet('LMKGPIO4')] p8: gap=33 ignorepadtopadclearanceinfootprint=FALSE except(0: Arc-Hole Track-Track Track-Hole SMDPad-Hole THPad-Hole Via-Hole Fill-Hole Poly-Hole Region-Hole Text-Hole; 12: SMDPad-SMDPad Via-Poly; 26.5: THPad-Poly THPad-Region)
Clearance Clearance_gpio3 [InPolygon vs InNet('LMKGPIO3')] p9: gap=33 ignorepadtopadclearanceinfootprint=FALSE except(0: Arc-Hole Track-Track Track-Hole SMDPad-Hole THPad-Hole Via-Hole Fill-Hole Poly-Hole Region-Hole Text-Hole; 12: SMDPad-SMDPad Via-Poly; 26.5: THPad-Poly THPad-Region)
Clearance Clearance_gpio2 [InPolygon vs InNet('LMKGPIO2')] p10: gap=33 ignorepadtopadclearanceinfootprint=FALSE except(0: Arc-Hole Track-Track Track-Hole SMDPad-Hole THPad-Hole Via-Hole Fill-Hole Poly-Hole Region-Hole Text-Hole; 12: SMDPad-SMDPad Via-Poly; 26.5: THPad-Poly THPad-Region)
Clearance Clearance_gpio1 [InPolygon vs InNet('LMKGPIO1')] p11: gap=33 ignorepadtopadclearanceinfootprint=FALSE except(0: Arc-Hole Track-Track Track-Hole SMDPad-Hole THPad-Hole Via-Hole Fill-Hole Poly-Hole Region-Hole Text-Hole; 12: SMDPad-SMDPad Via-Poly; 26.5: THPad-Poly THPad-Region)
Clearance Clearance_gpio0 [InPolygon vs InNet('LMKGPIO0')] p12: gap=33 ignorepadtopadclearanceinfootprint=FALSE except(0: Arc-Hole Track-Track Track-Hole SMDPad-Hole THPad-Hole Via-Hole Fill-Hole Poly-Hole Region-Hole Text-Hole; 12: SMDPad-SMDPad Via-Poly; 26.5: THPad-Poly THPad-Region)
Clearance Clearance_SCL [InPolygon vs InNet('SCL')] p13: gap=33 ignorepadtopadclearanceinfootprint=FALSE except(0: Arc-Hole Track-Track Track-Hole SMDPad-Hole THPad-Hole Via-Hole Fill-Hole Poly-Hole Region-Hole Text-Hole; 12: SMDPad-SMDPad Via-Poly; 26.5: THPad-Poly THPad-Region)
Clearance Clearance_SCL1 [InPolygon vs InNet('SCL1')] p14: gap=33 ignorepadtopadclearanceinfootprint=FALSE except(0: Arc-Hole Track-Track Track-Hole SMDPad-Hole THPad-Hole Via-Hole Fill-Hole Poly-Hole Region-Hole Text-Hole; 12: SMDPad-SMDPad Via-Poly; 26.5: THPad-Poly THPad-Region)
Clearance Clearance_SDA [InPolygon vs InNet('SDA')] p15: gap=33 ignorepadtopadclearanceinfootprint=FALSE except(0: Arc-Hole Track-Track Track-Hole SMDPad-Hole THPad-Hole Via-Hole Fill-Hole Poly-Hole Region-Hole Text-Hole; 12: SMDPad-SMDPad Via-Poly; 26.5: THPad-Poly THPad-Region)
Clearance Clearance_SDA1 [InPolygon vs InNet('SDA1')] p16: gap=33 ignorepadtopadclearanceinfootprint=FALSE except(0: Arc-Hole Track-Track Track-Hole SMDPad-Hole THPad-Hole Via-Hole Fill-Hole Poly-Hole Region-Hole Text-Hole; 12: SMDPad-SMDPad Via-Poly; 26.5: THPad-Poly THPad-Region)
Clearance Clearance_U2AGPIO0SDA [InPolygon vs InNet('U2AGPIO0/SDA')] p17: gap=33 ignorepadtopadclearanceinfootprint=FALSE except(0: Arc-Hole Track-Track Track-Hole SMDPad-Hole THPad-Hole Via-Hole Fill-Hole Poly-Hole Region-Hole Text-Hole; 12: SMDPad-SMDPad Via-Poly; 26.5: THPad-Poly THPad-Region)
Clearance Clearance_U2AGPIO1SCL [InPolygon vs InNet('U2AGPIO1/SCL')] p18: gap=33 ignorepadtopadclearanceinfootprint=FALSE except(0: Arc-Hole Track-Track Track-Hole SMDPad-Hole THPad-Hole Via-Hole Fill-Hole Poly-Hole Region-Hole Text-Hole; 12: SMDPad-SMDPad Via-Poly; 26.5: THPad-Poly THPad-Region)
Clearance Clearance_U2AGPIO4SIMO [InPolygon vs InNet('U2AGPIO4/SIMO')] p19: gap=33 ignorepadtopadclearanceinfootprint=FALSE except(0: Arc-Hole Track-Track Track-Hole SMDPad-Hole THPad-Hole Via-Hole Fill-Hole Poly-Hole Region-Hole Text-Hole; 12: SMDPad-SMDPad Via-Poly; 26.5: THPad-Poly THPad-Region)
Clearance Clearance_U2AGPIO2SCK [InPolygon vs InNet('U2AGPIO2/SCK')] p20: gap=33 ignorepadtopadclearanceinfootprint=FALSE except(0: Arc-Hole Track-Track Track-Hole SMDPad-Hole THPad-Hole Via-Hole Fill-Hole Poly-Hole Region-Hole Text-Hole; 12: SMDPad-SMDPad Via-Poly; 26.5: THPad-Poly THPad-Region)
Clearance Clearance_STAT0 [InPolygon vs InNet('STAT0')] p21: gap=33 ignorepadtopadclearanceinfootprint=FALSE except(0: Arc-Hole Track-Track Track-Hole SMDPad-Hole THPad-Hole Via-Hole Fill-Hole Poly-Hole Region-Hole Text-Hole; 12: SMDPad-SMDPad Via-Poly; 26.5: THPad-Poly THPad-Region)
Clearance Clearance_STAT1 [InPolygon vs InNet('STAT1')] p22: gap=33 ignorepadtopadclearanceinfootprint=FALSE except(0: Arc-Hole Track-Track Track-Hole SMDPad-Hole THPad-Hole Via-Hole Fill-Hole Poly-Hole Region-Hole Text-Hole; 12: SMDPad-SMDPad Via-Poly; 26.5: THPad-Poly THPad-Region)
Clearance Clearance_HWCTRL [InPolygon vs InNet('HWCTRL')] p23: gap=33 ignorepadtopadclearanceinfootprint=FALSE except(0: Arc-Hole Track-Track Track-Hole SMDPad-Hole THPad-Hole Via-Hole Fill-Hole Poly-Hole Region-Hole Text-Hole; 12: SMDPad-SMDPad Via-Poly; 26.5: THPad-Poly THPad-Region)
Clearance Clearance_PDN [InPolygon vs InNet('PDN')] p24: gap=33 ignorepadtopadclearanceinfootprint=FALSE except(0: Arc-Hole Track-Track Track-Hole SMDPad-Hole THPad-Hole Via-Hole Fill-Hole Poly-Hole Region-Hole Text-Hole; 12: SMDPad-SMDPad Via-Poly; 26.5: THPad-Poly THPad-Region)
Clearance CLEARANCE_LMKGPIO6 [InPolygon vs InNet('LMKGPIO6')] p25: gap=33 ignorepadtopadclearanceinfootprint=FALSE except(0: Arc-Hole Track-Track Track-Hole SMDPad-Hole THPad-Hole Via-Hole Fill-Hole Poly-Hole Region-Hole Text-Hole; 12: SMDPad-SMDPad Via-Poly; 26.5: THPad-Poly THPad-Region)
Clearance Clearance_Poly_BOTTOM [InPolygon vs OnLayer('Bottom Layer')] p26 off: gap=12 ignorepadtopadclearanceinfootprint=FALSE
Clearance Clearance_Poly_RF [InPolygon and (OnTopLayer or OnBottomLayer or OnLayer('L6-Mid-Layer 5 (G4)')) vs InxSignalClass('ttxOutputs') or InNetClass('OUT_LenMatch1a') or InNetClass('OUT_LenMatch2a') or InNetClass('XO_trace') or InNetClass('OUT_LenMatch1b') or InNetClass('OUT_LenMatch2b') or InNetClass('IN_trace') or InNet('D_N') or InNet('D_P')] p27: gap=33 ignorepadtopadclearanceinfootprint=FALSE
Clearance Clearance_Poly_Vcc [InPolygon and OnLayer('L3-Mid-Layer 2 (G1)')] p28: gap=33 ignorepadtopadclearanceinfootprint=FALSE except(12: Track-Track SMDPad-SMDPad THPad-Poly Via-Poly)
Clearance Clearance_Poly [InPolygon] p29: gap=12 ignorepadtopadclearanceinfootprint=FALSE
Clearance Clearance_FID [InComponentClass('FiducialMark') vs IsArc] p30: gap=0 ignorepadtopadclearanceinfootprint=FALSE
Clearance Clearance_BoardEdge_Poly [OnCopper and InPoly vs IsKeepOut] p31: gap=15 ignorepadtopadclearanceinfootprint=FALSE
Clearance Clearance_TPD4E004DRYR [InComponent('U6') vs InComponent('U6')] p32: gap=5 ignorepadtopadclearanceinfootprint=FALSE
Clearance Clearance_Keepouts [((IsTrack Or IsArc) And Not InPoly) And IsFree and IsKeepOut vs ((IsTrack Or IsArc) And Not InPoly) And IsFree and IsKeepOut] p33 off: gap=0 ignorepadtopadclearanceinfootprint=FALSE
Clearance Clearance_DiffTrace [InNetClass('OUT_LenMatch1a') or InNetClass('OUT_LenMatch2a') vs InNetClass('All Nets')] p34: gap=6 ignorepadtopadclearanceinfootprint=FALSE
Clearance Clearance_MTH [InComponent('MH1') vs InComponent('MH1')] p35 off: gap=0 ignorepadtopadclearanceinfootprint=TRUE
Clearance [All] p36: gap=7.87 ignorepadtopadclearanceinfootprint=FALSE except(0: Arc-Hole Track-Hole SMDPad-Hole THPad-Hole Via-Hole Fill-Hole Poly-Hole Region-Hole Text-Hole; 5: Track-Via; 5.8: SMDPad-SMDPad; 6.7: Track-SMDPad; 7: Track-Track; 7.2: Track-THPad SMDPad-THPad)
ComponentClearance ComponentClearance_SMT_TP [HasFootprint('TP_SM_1MM')] p1: gap=0 collisioncheckmode=3 verticalgap=0 showdistances=FALSE
ComponentClearance Shunts [HasFootprint('SNT-100-BK-G')] p2: gap=0 collisioncheckmode=3 verticalgap=0 showdistances=FALSE
ComponentClearance ComponentClearance_Shunt [InComponentClass('Header') vs InComponentClass('Shunt')] p3: gap=0 collisioncheckmode=3 verticalgap=0 showdistances=FALSE
ComponentClearance "Component Clearance_SMA_0603S" [HasFootprint('0603S') vs HasFootprint('0603S')] p4 off: gap=0 collisioncheckmode=3 verticalgap=0 showdistances=FALSE // 0603S option pads
ComponentClearance "JP26 to H3 clearance" [InComponent('H3') vs InComponent('JP26')] p5 off: gap=90 collisioncheckmode=3 verticalgap=10 showdistances=FALSE
ComponentClearance "4 way header" [HasFootprint('TSW-103-07-G-S') vs HasFootprint('TSW-101-07-G-S')] p6 off: gap=0 collisioncheckmode=3 verticalgap=10 showdistances=FALSE
ComponentClearance ComponentClearance_Y [InComponent('Y*') vs InComponent('Y*')] p7 off: gap=0 collisioncheckmode=3 verticalgap=0 showdistances=FALSE
ComponentClearance ComponentClearance_H_HS [InComponent('HS*') vs InComponent('H*')] p8 off: gap=0 collisioncheckmode=3 verticalgap=0 showdistances=FALSE
ComponentClearance ComponentClearance_XU1_U5 [InComponent('U11') vs InComponent('U5')] p9 off: gap=0 collisioncheckmode=3 verticalgap=0 showdistances=FALSE
ComponentClearance ComponentClearance_THtoTH [HasFootprint('TSW-103-07-G-S') vs HasFootprint('TSW-101-07-G-S')] p10 off: gap=30 collisioncheckmode=3 verticalgap=30 showdistances=FALSE // Pin 4 of 3-way jumper blcok
ComponentClearance ComponentClearance_MountingHoles_FiducialMarks [InComponentClass('Mounting Holes') vs InComponentClass('FiducialMark')] p11: gap=50 collisioncheckmode=3 verticalgap=10 showdistances=FALSE
ComponentClearance ComponentClearance_Shunt_1 [InComponent('SH8') vs InComponent('SH9')] p12 off: gap=0 collisioncheckmode=3 verticalgap=0 showdistances=FALSE
ComponentClearance ComponentClearance_Shunt_2 [InComponent('JP28') vs InComponentClass('Shunt')] p13 off: gap=0 collisioncheckmode=3 verticalgap=0 showdistances=FALSE
ComponentClearance ComponentClearance_Logo [InComponentClass('Logo')] p14: gap=50 collisioncheckmode=3 verticalgap=10 showdistances=FALSE
ComponentClearance ComponentClearance_ScrewToNut [(HasFootprint('NY PMS 440 0025 PH')) vs (HasFootprint('Keystone_1902C'))] p15: gap=5 collisioncheckmode=3 verticalgap=10 showdistances=FALSE
ComponentClearance ComponentClearance_MountingHoles [InComponentClass('Mounting Holes')] p16: gap=100 collisioncheckmode=3 verticalgap=100000 showdistances=FALSE
ComponentClearance ComponentClearance_SmallPassives [HasFootprint('0201*') or HasFootprint('0402*') or HasFootprint('0508') or HasFootprint('0603*') or HasFootprint('0612') or HasFootprint('0805*') or HasFootprint('0815*') or HasFootprint('0830*') or HasFootprint('1206*') or HasFootprint('1210*') or HasFootprint('1808*') or HasFootprint('1812*') or HasFootprint('1825*') or HasFootprint('2010*') or HasFootprint('2220*') or HasFootprint('2225*') or HasFootprint('2512*') or HasFootprint('2728*') or HasFootprint('3518*') vs HasFootprint('0201*') or HasFootprint('0402*') or HasFootprint('0508') or HasFootprint('0603*') or HasFootprint('0612') or HasFootprint('0805*') or HasFootprint('0815*') or HasFootprint('0830*') or HasFootprint('1206*') or HasFootprint('1210*') or HasFootprint('1808*') or HasFootprint('1812*') or HasFootprint('1825*') or HasFootprint('2010*') or HasFootprint('2220*') or HasFootprint('2225*') or HasFootprint('2512*') or HasFootprint('2728*') or HasFootprint('3518*')] p17: gap=12 collisioncheckmode=3 verticalgap=10 showdistances=FALSE
ComponentClearance ComponentClearance_THtoSMT [IsThruComponent vs IsSMTComponent] p18: gap=25 collisioncheckmode=3 verticalgap=30 showdistances=FALSE
ComponentClearance [All] p19: gap=10 collisioncheckmode=3 verticalgap=10 showdistances=FALSE
DiffPairsRouting DiffPairsRouting_Tight [InDifferentialPairClass('DiffTight')] p1: maxlimit=100 minlimit=6 mostfreqgap=8 toplayer_minwidth=7 toplayer_maxwidth=11 toplayer_prefwidth=8 midlayer2_minwidth=7 midlayer2_maxwidth=11 midlayer2_prefwidth=8 midlayer3_minwidth=7 midlayer3_maxwidth=11 midlayer3_prefwidth=8 midlayer4_minwidth=7 midlayer4_maxwidth=11 midlayer4_prefwidth=8 midlayer5_minwidth=5 midlayer5_maxwidth=11 midlayer5_prefwidth=8 midlayer6_minwidth=7 midlayer6_maxwidth=11 midlayer6_prefwidth=8 bottomlayer_minwidth=7 bottomlayer_maxwidth=11 bottomlayer_prefwidth=8 substack1={B49040B5-5527-468B-9398-C320261C25F3} toplayer_{b49040b5-5527-468b-9398-c320261c25f3}_minwidth=15 toplayer_{b49040b5-5527-468b-9398-c320261c25f3}_maxwidth=15 toplayer_{b49040b5-5527-468b-9398-c320261c25f3}_prefwidth=15 midlayer2_{b49040b5-5527-468b-9398-c320261c25f3}_minwidth=15 midlayer2_{b49040b5-5527-468b-9398-c320261c25f3}_maxwidth=15 midlayer2_{b49040b5-5527-468b-9398-c320261c25f3}_prefwidth=15 midlayer3_{b49040b5-5527-468b-9398-c320261c25f3}_minwidth=15 midlayer3_{b49040b5-5527-468b-9398-c320261c25f3}_maxwidth=15 midlayer3_{b49040b5-5527-468b-9398-c320261c25f3}_prefwidth=15 midlayer4_{b49040b5-5527-468b-9398-c320261c25f3}_minwidth=15 midlayer4_{b49040b5-5527-468b-9398-c320261c25f3}_maxwidth=15 midlayer4_{b49040b5-5527-468b-9398-c320261c25f3}_prefwidth=15 midlayer5_{b49040b5-5527-468b-9398-c320261c25f3}_minwidth=15 midlayer5_{b49040b5-5527-468b-9398-c320261c25f3}_maxwidth=15 midlayer5_{b49040b5-5527-468b-9398-c320261c25f3}_prefwidth=15 midlayer6_{b49040b5-5527-468b-9398-c320261c25f3}_minwidth=15 midlayer6_{b49040b5-5527-468b-9398-c320261c25f3}_maxwidth=15 midlayer6_{b49040b5-5527-468b-9398-c320261c25f3}_prefwidth=15 bottomlayer_{b49040b5-5527-468b-9398-c320261c25f3}_minwidth=15 bottomlayer_{b49040b5-5527-468b-9398-c320261c25f3}_maxwidth=15 bottomlayer_{b49040b5-5527-468b-9398-c320261c25f3}_prefwidth=15 maxuncoupledlength=500
DiffPairsRouting DiffPairsRouting_Uncoupled [InDifferentialPairClass('All Differential Pairs')] p2: maxlimit=1000 minlimit=4 mostfreqgap=33 toplayer_minwidth=7 toplayer_maxwidth=11 toplayer_prefwidth=11 midlayer2_minwidth=7 midlayer2_maxwidth=11 midlayer2_prefwidth=11 midlayer3_minwidth=7 midlayer3_maxwidth=11 midlayer3_prefwidth=11 midlayer4_minwidth=7 midlayer4_maxwidth=11 midlayer4_prefwidth=11 midlayer5_minwidth=5 midlayer5_maxwidth=11 midlayer5_prefwidth=11 midlayer6_minwidth=7 midlayer6_maxwidth=11 midlayer6_prefwidth=11 bottomlayer_minwidth=7 bottomlayer_maxwidth=11 bottomlayer_prefwidth=11 substack1={B49040B5-5527-468B-9398-C320261C25F3} toplayer_{b49040b5-5527-468b-9398-c320261c25f3}_minwidth=15 toplayer_{b49040b5-5527-468b-9398-c320261c25f3}_maxwidth=15 toplayer_{b49040b5-5527-468b-9398-c320261c25f3}_prefwidth=15 midlayer2_{b49040b5-5527-468b-9398-c320261c25f3}_minwidth=15 midlayer2_{b49040b5-5527-468b-9398-c320261c25f3}_maxwidth=15 midlayer2_{b49040b5-5527-468b-9398-c320261c25f3}_prefwidth=15 midlayer3_{b49040b5-5527-468b-9398-c320261c25f3}_minwidth=15 midlayer3_{b49040b5-5527-468b-9398-c320261c25f3}_maxwidth=15 midlayer3_{b49040b5-5527-468b-9398-c320261c25f3}_prefwidth=15 midlayer4_{b49040b5-5527-468b-9398-c320261c25f3}_minwidth=15 midlayer4_{b49040b5-5527-468b-9398-c320261c25f3}_maxwidth=15 midlayer4_{b49040b5-5527-468b-9398-c320261c25f3}_prefwidth=15 midlayer5_{b49040b5-5527-468b-9398-c320261c25f3}_minwidth=15 midlayer5_{b49040b5-5527-468b-9398-c320261c25f3}_maxwidth=15 midlayer5_{b49040b5-5527-468b-9398-c320261c25f3}_prefwidth=15 midlayer6_{b49040b5-5527-468b-9398-c320261c25f3}_minwidth=15 midlayer6_{b49040b5-5527-468b-9398-c320261c25f3}_maxwidth=15 midlayer6_{b49040b5-5527-468b-9398-c320261c25f3}_prefwidth=15 bottomlayer_{b49040b5-5527-468b-9398-c320261c25f3}_minwidth=15 bottomlayer_{b49040b5-5527-468b-9398-c320261c25f3}_maxwidth=15 bottomlayer_{b49040b5-5527-468b-9398-c320261c25f3}_prefwidth=15 maxuncoupledlength=500
FabricationTestPointUsage TestPointUsage [All] p1: valid=2 allowmultiple=FALSE
FabricationTestpoint Testpoint [All] p1: side=3 testpointundercomponent=TRUE minsize=40 maxsize=100 preferedsize=60 minholesize=0 maxholesize=40 preferedholesize=32 testpointgrid=1 allowsidetop=TRUE allowsidebottom=TRUE usegrid=TRUE gridtolerance=0.01
FanoutControl Fanout_LCC [IsLCC] p1: bgadir=Out bgaviamode=Centered fanoutstyle=Auto fanoutdirection=Alternating viagrid=1 // Fanout_LCC (Default Rule)
FanoutControl Fanout_BGA [IsBGA] p2: bgadir=Out bgaviamode=Centered fanoutstyle=Auto fanoutdirection=Alternating viagrid=1 // Fanout_BGA (Default Rule)
FanoutControl Fanout_Default [All] p4: bgadir=Out bgaviamode=Centered fanoutstyle=Auto fanoutdirection=Alternating viagrid=1 // Fanout_Default (Default Rule)
FanoutControl Fanout_Small [(CompPinCount < 5)] p5: bgadir=Out bgaviamode=Centered fanoutstyle=Auto fanoutdirection=OutThenIn viagrid=1 // Fanout_Small (Default Rule)
HoleSize [All] p1: absolutevalues=TRUE maxlimit=251 minlimit=7.87 maxpercent=80.000 minpercent=20.000
HoleToHoleClearance HoleToHoleClearance_1 [InComponent('MH1') vs InComponent('MH1')] p1: gap=9 allowstackedmicrovias=TRUE
HoleToHoleClearance [All] p2: gap=10 allowstackedmicrovias=TRUE
MatchedLengths HS_Outputs_ttx [InxSignalClass('ttxOutputs')] p1: tolerance=5 checknetsindiffpair=FALSE checkdiffpairvsdiffpair=TRUE checkxsignals=TRUE checkothers=TRUE
MatchedLengths HS_Outputs_ttx_Diff [InxSignalClass('ttxOutputs')] p2: tolerance=1 checknetsindiffpair=TRUE checkdiffpairvsdiffpair=FALSE checkxsignals=FALSE checkothers=FALSE
MatchedLengths HS_Inputs_ttx [InxSignalClass('ttxInputs')] p3: tolerance=5 checknetsindiffpair=FALSE checkdiffpairvsdiffpair=TRUE checkxsignals=TRUE checkothers=TRUE
MatchedLengths HS_Inputs_ttx_Diff [InxSignalClass('ttxInputs')] p4: tolerance=1 checknetsindiffpair=TRUE checkdiffpairvsdiffpair=FALSE checkxsignals=FALSE checkothers=FALSE
MaxMinImpedance "Schematic Impedance Constraint_21" [InNet('R_IN1_P')] p1: minimum=45.00 maximum=55.00
MaxMinImpedance "Schematic Impedance Constraint_20" [InNetClass('OUT_LenMatch1b')] p2: minimum=45.00 maximum=55.00
MaxMinImpedance "Schematic Impedance Constraint_19" [InNetClass('OUT_LenMatch2a')] p3: minimum=45.00 maximum=55.00
MaxMinImpedance "Schematic Impedance Constraint_18" [InNet('R_IN0_N')] p4: minimum=45.00 maximum=55.00
MaxMinImpedance "Schematic Impedance Constraint_17" [InNet('R_IN0_P')] p5: minimum=45.00 maximum=55.00
MaxMinImpedance "Schematic Impedance Constraint_16" [InNet('SMA_IN0_P')] p6: minimum=45.00 maximum=55.00
MaxMinImpedance "Schematic Impedance Constraint_15" [InNetClass('OUT_LenMatch1a')] p7: minimum=45.00 maximum=55.00
MaxMinImpedance "Schematic Impedance Constraint_14" [InNet('SMA_IN3_P')] p8: minimum=45.00 maximum=55.00
MaxMinImpedance "Schematic Impedance Constraint_13" [InNet('R_IN2_P')] p9: minimum=45.00 maximum=55.00
MaxMinImpedance "Schematic Impedance Constraint_12" [InNet('IN3_P')] p10: minimum=45.00 maximum=55.00
MaxMinImpedance "Schematic Impedance Constraint_11" [InNet('SMA_IN3_N')] p11: minimum=45.00 maximum=55.00
MaxMinImpedance "Schematic Impedance Constraint_10" [InNetClass('OUT_LenMatch2b')] p12: minimum=45.00 maximum=55.00
MaxMinImpedance "Schematic Impedance Constraint_9" [InNet('IN3_N')] p13: minimum=45.00 maximum=55.00
MaxMinImpedance "Schematic Impedance Constraint_8" [InNet('SMA_IN1_P')] p14: minimum=45.00 maximum=55.00
MaxMinImpedance "Schematic Impedance Constraint_7" [InNet('SMA_IN1_N')] p15: minimum=45.00 maximum=55.00
MaxMinImpedance "Schematic Impedance Constraint_6" [InNet('SMA_IN2_P')] p16: minimum=45.00 maximum=55.00
MaxMinImpedance "Schematic Impedance Constraint_5" [InNet('R_IN1_N')] p17: minimum=45.00 maximum=55.00
MaxMinImpedance "Schematic Impedance Constraint_4" [InNet('R_IN2_N')] p18: minimum=45.00 maximum=55.00
MaxMinImpedance "Schematic Impedance Constraint_3" [InNet('SMA_IN0_N')] p19: minimum=45.00 maximum=55.00
MaxMinImpedance "Schematic Impedance Constraint_1" [InNet('SMA_IN2_N')] p20: minimum=45.00 maximum=55.00
MaxMinImpedance "Schematic Impedance Constraint_31" [InNet('LMKGPIO2')] p21: minimum=45.00 maximum=55.00
MaxMinImpedance "Schematic Impedance Constraint_28" [InNet('LMKSCS_ADD')] p22: minimum=45.00 maximum=55.00
MaxMinImpedance "Schematic Impedance Constraint_66" [InNet('XO2_P')] p23: minimum=45.00 maximum=55.00
MaxMinImpedance "Schematic Impedance Constraint_168" [InNet('U2AGPIO8')] p24: minimum=45.00 maximum=55.00
MaxMinImpedance "Schematic Impedance Constraint_167" [InNet('U2AGPIO7')] p25: minimum=45.00 maximum=55.00
MaxMinImpedance "Schematic Impedance Constraint_165" [InNet('U2AGPIO5/SOMI')] p26: minimum=45.00 maximum=55.00
MaxMinImpedance "Schematic Impedance Constraint_157" [InNet('LMKSDIO')] p27: minimum=45.00 maximum=55.00
MaxMinImpedance "Schematic Impedance Constraint_155" [InNet('LMKSCK')] p28: minimum=45.00 maximum=55.00
MaxMinImpedance "Schematic Impedance Constraint_150" [InNet('LMKPDN')] p29: minimum=45.00 maximum=55.00
MaxMinImpedance "Schematic Impedance Constraint_149" [InNet('LMKGPIO1')] p30: minimum=45.00 maximum=55.00
MaxMinImpedance "Schematic Impedance Constraint_148" [InNet('LMKGPIO0')] p31: minimum=45.00 maximum=55.00
MinimumAnnularRing MinimumAnnularRing_ThermalPadVias [IsVia and InAnyComponent] p1: minimumring=5.91
MinimumAnnularRing [All] p2: minimumring=0
MinimumSolderMaskSliver MinimumSolderMaskSliver_Logo [InComponentClass('Logo') vs InComponentClass('Logo')] p1: minsoldermaskwidth=0.7
MinimumSolderMaskSliver [All] p2: minsoldermaskwidth=2.5
PlaneClearance PlaneClearance_RF_vias [InNetClass('OUT_LenMatch2a')] p1: clearance=13
PlaneClearance PlaneClearance_RF_vias_1 [InNetClass('OUT_LenMatch1a')] p2: clearance=13
PlaneClearance [All] p3: clearance=20
PlaneConnect [All] p1: planeconnectstyle=Direct reliefexpansion=10 reliefentries=4 reliefconductorwidth=10 reliefairgap=10
PolygonConnect [All] p1: thpad.connectstyle=Direct thpad.reliefconductorwidth=10 thpad.reliefentries=4 thpad.polygonreliefangle="90 Angle" thpad.airgapwidth=10 smdpad.connectstyle=Relief smdpad.reliefconductorwidth=10 smdpad.reliefentries=4 smdpad.polygonreliefangle="90 Angle" smdpad.airgapwidth=10 via.connectstyle=Direct via.reliefconductorwidth=10 via.reliefentries=4 via.polygonreliefangle="90 Angle" via.airgapwidth=10
RoutingVias RoutingVias_MTH [IsVia and InComponent('MH1')] p1: holewidth=10 width=20 viastyle="Through Hole" minholewidth=10 minwidth=20 maxholewidth=100 maxwidth=140
RoutingVias ThermalPadVias [IsVia and InAnyComponent] p2: holewidth=7.87 width=19.68 viastyle="Through Hole" minholewidth=7.87 minwidth=19 maxholewidth=12.99 maxwidth=137
RoutingVias [All] p3: holewidth=10 width=20 viastyle="Through Hole" minholewidth=10 minwidth=18 maxholewidth=100 maxwidth=140
ShortCircuit ShortCircuit_MH1 [InComponent('MH1') vs InComponent('MH1')] p1: allowed=TRUE
ShortCircuit [All] p2: allowed=FALSE
SilkToBoardRegionClearance [Not ((IsComment or IsDesignator) And (Hide <> 'False')) and not InRegion(1000,500,4000,800)] p1:
SilkToSilkClearance SilkToSilkClearance_Pb-FreeLogo [(HasFootprint('Pb-Free_Overlay_Medium') OR HasFootprint('Pb-Free_Overlay_Small')) vs (HasFootprint('Pb-Free_Overlay_Medium') OR HasFootprint('Pb-Free_Overlay_Small'))] p1: silktosilkclearance=0
SilkToSilkClearance [All] p2: silktosilkclearance=4
SilkToSolderMaskClearance [IsPad] p1: minsilkscreentomaskgap=3.9 clearancetoexposedcopper=TRUE
SilkToSolderMaskClearance SilkToComponentPadClearance [IsPad and InComponent('U5')] p2: minsilkscreentomaskgap=4 clearancetoexposedcopper=TRUE // U5
SilkToSolderMaskClearance "Silk to Solder Mask Opening" [All] p3: minsilkscreentomaskgap=3.9 clearancetoexposedcopper=FALSE
SolderMaskExpansion [All] p1: expansion=1.97 istentingtop=FALSE
Width [All] p1: maxlimit=200 minlimit=5 preferedwidth=10 midlayer5_prefwidth=5 substack1={B49040B5-5527-468B-9398-C320261C25F3} minimp=50.000000 maximp=50.000000 favimp=50.000000 checkconnectedcopper=TRUE
12 further rules are at their usual default settings.

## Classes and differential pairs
component class DC216A_Inputs: C125 C126 C127 C128 J4 J5 J6 J7 J37 J38 J39 J40 R26 R27 R28 R29 R30 R31 R32 R33 R34 R35 R36 R37 R38 R39 R126 R130 R136 R137 R138 R139 R140 R141 R142 R143 R192 R193
component class DC216A_Power_Alternate: C1 C2 C7 C8 C9 C13 C154 C155 R1 R2 R3 R5 R201 R202 U10 U11
component class DC216A_Power: C6 C10 C21 C22 C23 C24 C27 C156 C500 C501 C502 C503 C504 C505 C506 C507 C508 C509 C510 C511 C512 C513 C514 C515 C516 D1 D2 J2 J3 J500 JP1 JP2 JP4 L500 L501 L502 L503 R8 R9 R203 R500 R501 R502 R504 SH1 SH2 SH4 TP1 TP2 TP4 TP5 TP7 TP501 U9 U500
net class OUT_LenMatch2b: SMA_O4_N SMA_O4_P SMA_O5_N SMA_O5_P SMA_O6_N SMA_O6_P SMA_O8_N SMA_O8_P SMA_O9_N SMA_O9_P
net class OUT_LenMatch2a: OUT4_A_N OUT4_A_P OUT5_A_N OUT5_A_P OUT6_A_N OUT6_A_P OUT8_A_N OUT8_A_P OUT9_A_N OUT9_A_P
net class OUT_LenMatch1b: SMA_O0_N SMA_O0_P SMA_O1_N SMA_O1_P SMA_O2_N SMA_O2_P SMA_O3_N SMA_O3_P SMA_O7_N SMA_O7_P SMA_O10_N SMA_O10_P SMA_O11_N SMA_O11_P SMA_O12_N SMA_O12_P SMA_O13_N SMA_O13_P
component class DC216A_Hardware: FID1 FID2 FID3 FID4 FID5 FID6 H1 H2 H3 H4 H5 H6 LBL1 Logo2 Logo4 MH1 ZZ1 ZZ2 ZZ3 ZZ4 ZZ5 ZZ6 ZZ7
component class DC216A_DUT: C61 C62 C63 C64 C65 C66 C67 C68 C69 C70 C71 C72 C73 C74 C75 C76 C77 J8 R40 R41 R42 TP27 TP28 TP29 U1
component class DC216A_Outputs_A: C98 C99 C100 C101 C102 C103 C104 J9 J10 J11 J12 J13 J14 J15 J16 R6 R7 R10 R78 R79 R80 R81 R82 R83 R84 R85 R86 R87 R88 R90 R92 R128 R132 R167 R168 R170 R171 R172 R173 R174
component class DC216A_Outputs_B: C105 C106 C107 C108 C109 C110 C111 C112 C113 C114 C115 C116 J17 J18 J19 J20 J21 J22 J23 J24 J25 J26 J27 J28 R89 R91 R93 R94 R95 R96 R97 R98 R99 R100 R101 R102 R103 R104 R105 R106 R107 R108 R109 R111 R113 R115 R117 R119 R175 R176 R177 R178 R179 R180 R181 R182 R183 R184 R204 R205
component class DC216A_PowerDist: C28 C29 C30 C31 C32 C33 C34 C35 C36 C37 C38 C39 C40 C41 C42 C43 C44 C45 C46 C47 C48 C49 C50 C51 C52 C53 C54 C55 C56 C57 C58 C59 C60 D3 D4 D5 FB1 FB2 FB3 FB4 FB5 FB6 FB7 FB8 FB9 FB10 FB11 NT1 R11 R12 R13 R14 R15 R16 R17 R18 R19 R20 R21 R22 R24 R25 R? TP8 TP9 TP10 TP11 TP12 TP13 TP14 TP15 TP16 TP17 TP18 TP19 TP20 TP21 TP22 TP23 TP24 TP25 TP26
component class DC216A_USB2ANY: C97 C129 C130 C131 C132 C133 C134 C135 C136 C137 C138 C139 C140 C141 C142 C143 C144 D11 D12 FB13 J41 J42 Q5 R144 R145 R146 R147 R148 R149 R150 R151 R152 R153 R154 R155 R156 R157 R158 R159 R160 R161 R162 R163 R164 R165 R166 R212 S6 TP41 U6 U7 U8 Y6
component class DC216A_Logic: C88 C89 C90 C91 C92 C93 C94 C95 C96 D6 D7 D8 D9 D10 JP5 Q1 Q2 Q3 Q4 R51 R52 R53 R54 R55 R56 R57 R58 R59 R60 R61 R62 R63 R64 R65 R66 R67 R68 R69 R70 R71 R72 R73 R74 R75 R76 R77 S1 S2 S3 S4 S5 SH5 SH6 TP31 TP32 TP33 TP34 TP35 TP36 TP37 TP38 TP39 TP40 U5
component class DC216A_Outputs_C: C117 C118 C119 C120 C121 C122 C123 C124 J29 J30 J31 J32 J33 J34 J35 J36 R110 R112 R114 R116 R118 R120 R121 R122 R123 R124 R125 R127 R129 R131 R133 R134 R135 R185 R186 R187 R188 R189 R190 R191
component class AssemblyNote: ZZ1 ZZ2 ZZ3 ZZ4 ZZ5 ZZ6 ZZ7
component class FiducialMark: FID1 FID2 FID3 FID4 FID5 FID6
component class Header: JP1 JP2 JP4
component class Label: LBL1
component class Shunt: SH1 SH2 SH4 SH5 SH6
component class DC216A_XO: C78 C79 C80 C81 C82 C83 C84 C85 C86 C87 FB12 R43 R44 R45 R46 R47 R48 R49 R50 R206 R207 R208 R209 R210 R211 TP30 U4 Y1 Y2 Y3 Y4 Y5
net class OUT_LenMatch1a: OUT0_A_N OUT0_A_P OUT1_A_N OUT1_A_P OUT2_A_N OUT2_A_P OUT3_A_N OUT3_A_P OUT7_A_N OUT7_A_P OUT10_A_N OUT10_A_P OUT11_A_N OUT11_A_P OUT12_A_N OUT12_A_P OUT13_A_N OUT13_A_P
net class XO_trace: NetR46_2 NetR47_2 NetR48_2 NetR49_2 NetR50_2 OUT_XO SMA_XO_P XO XO1_P XO2_P XO3
net class IN_trace: IN0_N IN0_P IN1_N IN1_P IN2_N IN2_P IN3_N IN3_P R_IN0_N R_IN0_P R_IN1_N R_IN1_P R_IN2_N R_IN2_P SMA_IN0_N SMA_IN0_P SMA_IN1_N SMA_IN1_P SMA_IN2_N SMA_IN2_P SMA_IN3_N SMA_IN3_P

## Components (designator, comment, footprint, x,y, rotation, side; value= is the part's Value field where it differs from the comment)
C1 "Capacitor" 0603 6191.2,2238.4 r90 bottom value=10uF
C2 "Capacitor" 0603 5925.2,1801.4 r0 bottom value=10uF
C6 "Capacitor" 0603 4916,5104 r180 top value=1uF
C7 "Capacitor" 0603 5987.2,2232.4 r90 bottom value=10uF
C8 "Capacitor" 0603 6627.2,2040.4 r270 bottom value=10uF
C9 "Capacitor" 0603 6195.2,1939.4 r90 bottom value=10uF
C10 "GRM21BR61A476ME15L" 0805_HV 6005.2,678.49 r90 top value=47uF
C13 "Capacitor" 0603 6634.2,1863.4 r270 bottom value=10uF
C21 "Capacitor" 0603 5017.76,1400.68 r90 top value=1uF
C22 "Capacitor" 0603 5200,2964 r90 bottom value=10uF
C23 "Capacitor" 0603 4946,2944 r90 bottom value=10uF
C24 "Capacitor" 0603 5279,2807 r90 bottom value=10uF
C27 "GRM21BR61A476ME15L" 0805_HV 5488.12,1336.34 r180 top value=47uF
C28 "Capacitor" 0603L 3859.83,6537.74 r180 top value=0.1uF
C29 "Capacitor" 0603L 3861.17,6433.67 r180 top value=10uF
C30 "Capacitor" 0402L 3679.34,5649.19 r180 top value=0.1uF
C31 "Capacitor" 0603L 2893.54,4873.64 r135 top value=0.1uF
C32 "Capacitor" 0603L 2966.3,4944.43 r135 top value=10uF
C33 "Capacitor" 0402L 3288.5,5215.14 r45 top value=0.1uF
C34 "Capacitor" 0603L 3679.17,6454.21 r0 top value=0.1uF
C35 "Capacitor" 0603L 3679.17,6344.14 r0 top value=10uF
C36 "Capacitor" 0402L 3587.68,5720.91 r225 top value=0.1uF
C37 "Capacitor" 0603L 3286.09,4524.1 r0 top value=0.1uF
C38 "Capacitor" 0603L 3286.09,4623.46 r0 top value=10uF
C39 "Capacitor" 0402L 3583.48,5156.19 r135 top value=0.1uF
C40 "Capacitor" 0603L 3517.14,6166.96 r180 top value=0.1uF
C41 "C0603C105K8PACTU" 0603L 3517.14,6060.78 r180 top value=1uF
C42 "Capacitor" 0402L 3476.04,5751.15 r270 top value=0.1uF
C43 "Capacitor" 0603L 4238.63,5506.03 r270 top value=0.1uF
C44 "Capacitor" 0603L 4133,5506.03 r270 top value=10uF
C45 "Capacitor" 0402L 3768.93,5519.89 r180 top value=0.1uF
C46 "Capacitor" 0603L 3594.36,4656.73 r0 top value=0.1uF
C47 "Capacitor" 0603L 3594.36,4756.58 r0 top value=10uF
C48 "Capacitor" 0402L 3494.26,5162.2 r135 top value=0.1uF
C49 "Capacitor" 0603L 2734.38,5551.05 r90 top value=0.1uF
C50 "Capacitor" 0603L 2840.69,5550.74 r90 top value=10uF
C51 "Capacitor" 0402L 3175.06,5503.81 r315 top value=0.1uF
C52 "Capacitor" 0603L 4191.67,5219.67 r90 top value=0.1uF
C53 "Capacitor" 0603L 4084.77,5219.67 r90 top value=10uF
C54 "Capacitor" 0402L 3714.08,5388.23 r135 top value=0.1uF
C55 "Capacitor" 0603L 3294.94,6239.95 r180 top value=0.1uF
C56 "Capacitor" 0603L 3294.94,6133.77 r180 top value=10uF
C57 "Capacitor" 0402L 3390.25,5743.49 r315 top value=0.1uF
C58 "Capacitor" 0603L 3177.13,6077.89 r180 top value=0.1uF
C59 "Capacitor" 0603L 3177.13,5973.89 r180 top value=10uF
C60 "Capacitor" 0402L 3321.17,5685.83 r315 top value=0.1uF
C61 "C1608X7R1H104K080AA" 0603L 3526.25,5843.69 r90 top value=0.1uF
C62 "Capacitor" 0603L 3498.59,5081.45 r315 top value=10uF
C63 "Capacitor" 0603L 3847.48,5311.17 r315 top value=10uF
C64 "Capacitor" 0603L 3822.35,5265.86 r315 top value=10uF
C65 "Capacitor" 0603L 3797.22,5220.56 r315 top value=10uF
C66 "Capacitor" 0603L 3258.74,5687.24 r135 top value=10uF
C67 "C0603C104J3RACTU" 0603 3471.84,4980.42 r270 top value=0.1uF
C68 "C0805C473J3GACTU" 0805_150 3630.35,4976.1 r180 bottom value=0.047uF
C69 "C3225C0G1H104J250AA" 1210_280 3660.69,4874.62 r0 bottom value=0.1uF
C70 "C0603C104J3RACTU" 0603S 3479,3209.05 r90 top value=0.1uF
C71 "C0603C104J3RACTU" 0603S 3509,3282.4 r0 top value=0.1uF
C72 "C0603C104J3RACTU" 0603 3971.3,5137.8 r315 top value=0.1uF
C73 "Capacitor" 0805_150 4056.2,5042.97 r225 bottom value=0.047uF
C74 "C3225C0G1H104J250AA" 1210_280 4154.47,4985.89 r45 bottom value=0.1uF
C75 "GRM188R71A474KA61D" 0603 3145.77,5741.54 r180 top value=0.47uF
C76 "Capacitor" 0805_150 3056.5,5900.08 r225 bottom value=0.047uF
C77 "C3225C0G1H104J250AA" 1210_280 2997.37,5988.36 r45 bottom value=0.1uF
C78 "Capacitor" 0603 4392.26,3032.57 r0 top value=0.1uF
C79 "Capacitor" 0603 4480.99,3317.89 r270 top value=10uF
C80 "Capacitor" 0603 4426.24,3317.63 r90 top value=0.1uF
C81 "Capacitor" 0603 4164.19,3166.46 r0 top value=0.1uF
C82 "Capacitor" 0603 3959.86,2985.56 r0 top value=0.1uF
C83 "Capacitor" 0603 3727.64,3624.84 r180 top value=0.1uF
C84 "Capacitor" 0603 3807.55,3873.81 r0 bottom value=0.1uF
C85 "Capacitor" 0603 3672.72,2422.5 r90 bottom value=0.1uF
C86 "Capacitor" 0603 4081.38,3722.29 r270 bottom value=100pF
C87 "Capacitor" 0603 3729.54,3089.71 r270 top value=0.1uF
C88 "Capacitor" 0603 3076,872 r90 top value=100pF
C89 "Capacitor" 0603 1611.32,2520.22 r180 top value=0.1uF
C90 "Capacitor" 0603 1830.04,2275.2 r0 top value=0.01uF
C91 "Capacitor" 0603 3083,1617 r90 top value=100pF
C92 "Capacitor" 0603 1429.04,2053.68 r270 top value=33pF
C93 "Capacitor" 0603 1706,2116 r90 top value=33pF
C94 "06031A330JAT2A" 0603 2409,2361 r0 top value=33pF
C95 "Capacitor" 0603 3074,2386 r90 top value=100pF
C96 "C0603C104J3RACTU" 0603 521.16,2047.25 r0 top value=0.1uF
C97 "Capacitor" 0603 1523,1418 r0 bottom value=10uF
C98 "GRM155R71E104KE14D" 0402L 351,2612.5 r0 top value=0.1uF
C100 "GRM155R71E104KE14D" 0402L 351,3112.5 r0 top value=0.1uF
C101 "GRM155R71E104KE14D" 0402L 6647,2612.5 r180 top value=0.1uF
C102 "GRM155R71E104KE14D" 0402L 6647,4112.5 r180 top value=0.1uF
C103 "GRM155R71E104KE14D" 0402L 6647,3112.5 r180 top value=0.1uF
C104 "GRM155R71E104KE14D" 0402L 6647,3612.5 r180 top value=0.1uF
C105 "GRM155R71E104KE14D" 0402L 6647,6112.5 r180 top value=0.1uF
C106 "GRM155R71E104KE14D" 0402L 6647,4612.5 r180 top value=0.1uF
C107 "GRM155R71E104KE14D" 0402L 6647,5612.5 r180 top value=0.1uF
C108 "GRM155R71E104KE14D" 0402L 6647,5112.5 r180 top value=0.1uF
C109 "GRM155R71E104KE14D" 0402L 6647,6612.5 r180 top value=0.1uF
C110 "GRM155R71E104KE14D" 0402L 6647,8112.5 r180 top value=0.1uF
C111 "GRM155R71E104KE14D" 0402L 6647,7112.5 r180 top value=0.1uF
C112 "GRM155R71E104KE14D" 0402L 6647,7612.5 r180 top value=0.1uF
C113 "GRM155R71E104KE14D" 0402L 2247.5,8810 r270 top value=0.1uF
C114 "GRM155R71E104KE14D" 0402L 747.5,8810 r270 top value=0.1uF
C115 "GRM155R71E104KE14D" 0402L 1747.5,8810 r270 top value=0.1uF
C116 "GRM155R71E104KE14D" 0402L 1247.5,8810 r270 top value=0.1uF
C117 "GRM155R71E104KE14D" 0402L 351,8112.5 r0 top value=0.1uF
C118 "GRM155R71E104KE14D" 0402L 351,6612.5 r0 top value=0.1uF
C119 "GRM155R71E104KE14D" 0402L 351,7612.5 r0 top value=0.1uF
C120 "GRM155R71E104KE14D" 0402L 351,7112.5 r0 top value=0.1uF
C121 "GRM155R71E104KE14D" 0402L 351,6112.5 r0 top value=0.1uF
C122 "GRM155R71E104KE14D" 0402L 351,4612.5 r0 top value=0.1uF
C123 "GRM155R71E104KE14D" 0402L 351,5612.5 r0 top value=0.1uF
C124 "GRM155R71E104KE14D" 0402L 351,5112.5 r0 top value=0.1uF
C129 "Capacitor" 0603 907.96,1086.62 r180 top value=10uF
C130 "Capacitor" 0603 1039,1173.01 r90 top value=10uF
C131 "Capacitor" 0805 755.13,1046.47 r90 top value=22uF
C132 "Capacitor" 0603 733,1207 r0 top value=0.1uF
C133 "Capacitor" 0603 434.1,901.79 r270 top value=0.1uF
C134 "Capacitor" 0603 689.47,1054.22 r270 top value=220pF
C135 "Capacitor" 0603 1012.71,811.85 r270 top value=30pF
C136 "Capacitor" 0603 1017.71,501.85 r90 top value=30pF
C137 "Capacitor" 0603 1217.71,246.85 r90 top value=0.1uF
C138 "Capacitor" 0603 1327.71,246.85 r90 top value=0.1uF
C139 "Capacitor" 0603 1121.21,221.85 r180 top value=2200pF
C140 "Capacitor" 0603 1305.71,750.85 r270 top value=220pF
C141 "Capacitor" 0603 1877.05,246.85 r90 top value=0.47uF
C142 "Capacitor" 0603 1687.71,246.85 r90 top value=0.1uF
C143 "Capacitor" 0603 1822.71,246.85 r90 top value=0.1uF
C144 "Capacitor" 0603 1682.71,1041.85 r270 top value=0.1uF
C154 "Capacitor" 0603 6105.2,2073.4 r270 bottom value=0.01uF
C155 "Capacitor" 0603 6580.2,1862.4 r270 bottom value=0.01uF
C156 "Capacitor" 0603 5286,2631 r270 bottom value=0.01uF
C500 "T495X476K035ATE300" 7343-43 6347.6,995.9 r180 top value=47uF
C501 "C2012X7S1A226M125AC" 0805L 6158.5,1584.4 r0 top value=22uF
C502 "C2012X7S1A226M125AC" 0805L 6158.5,1510.6 r0 top value=22uF
C503 "C2012X7S1A226M125AC" 0805L 6158.5,1434.1 r0 top value=22uF
C504 "GRM155R71E222KA01D" 0402 5543.6,845.4 r270 top value=2200pF
C505 "C2012X7S1E106K125AC" FP-C2012X7S1E106K125AC_0805-MFG 6331.8,1360.5 r0 top
C506 "C2012X7S1E106K125AC" FP-C2012X7S1E106K125AC_0805-MFG 6331.8,1299.4 r0 top
C507 "GRM155R71E222KA01D" 0402 6344.3,1480.3 r180 top value=2200pF
C508 "C2012X7S1A226M125AC" 0805L 6158.5,1276.1 r0 top value=22uF
C509 "C2012X7S1A226M125AC" 0805L 6158.5,1202.9 r0 top value=22uF
C510 "C2012X7S1A226M125AC" 0805L 6158.5,1130 r0 top value=22uF
C511 "UMK105CG271JV-F" 0402 6532.6,1601.2 r90 top
C512 "C1608X7R1E474K080AE" 0603 6517.1,1506.3 r0 top value=0.47uF
C513 "GRM188Z71A106MA73D" 0603 5740.8,1410.1 r270 top value=10uF
C514 "GRM155R71E222KA01D" 0402 5673.9,1413.1 r270 top value=2200pF
C515 "GRM188Z71A106MA73D" 0603 5289.4,2174.7 r270 top value=10uF
C516 "GRM155R71E222KA01D" 0402 5114.2,2179.9 r270 top value=2200pF
D1 "DIODE_SCHOTTKY" SMA 5866.47,704.98 r90 top value=20V
D2 "DIODE_SCHOTTKY" SMA 6091.34,367.61 r270 top value=20V
D3 "VDD PWR" LED_LTST-C190 4706.69,1983.98 r0 top value=Green
D4 "VDDO PWR" LED_LTST-C190 4708.01,1909.24 r0 top value=Green
D5 "XO PWR" LED_LTST-C190 4704.87,2062.98 r0 top value=Green
D6 "SCLK BUSY" LED_LTST-C170_Red 4695.56,1741.67 r0 top value=Red
D7 "GPIO0=HI" LED_LTST-C170 3390,450 r180 top value=Yellow
D8 "DIODE_BAT54" SOT-23 1725.41,2386.9 r0 top value=30V
D9 "GPIO1=HI" LED_LTST-C170 3390.51,1192.08 r180 top value=Yellow
D10 "GPIO2=HI" LED_LTST-C170 3391,1978 r180 top value=Yellow
D11 "Zener" SMB 567.86,991.65 r90 top value=7.5V
D12 "USB" LED_LTST-C190 4712.1,1828.85 r0 top value=Green
FB1 "BLM18SG221TN1D" 0603L 3859.87,6486.34 r0 top value="220 ohm"
FB2 "BLM18SG221TN1D" 0603L 2931.46,4908.73 r315 top value="220 ohm"
FB3 "BLM18SG221TN1D" 0603L 3679.17,6399.18 r180 top value="220 ohm"
FB4 "BLM18SG221TN1D" 0603L 3286.09,4573.78 r180 top value="220 ohm"
FB5 "BLM18SG221TN1D" 0603L 3517.14,6113.87 r0 top value="220 ohm"
FB6 "BLM18SG221TN1D" 0603L 4185.81,5506.03 r90 top value="220 ohm"
FB7 "BLM18SG221TN1D" 0603L 3594.36,4706.65 r180 top value="220 ohm"
FB8 "BLM18SG221TN1D" 0603L 2787.53,5550.9 r270 top value="220 ohm"
FB9 "BLM18SG221TN1D" 0603L 4138.22,5219.67 r270 top value="220 ohm"
FB10 "BLM18SG221TN1D" 0603L 3294.94,6186.86 r0 top value="220 ohm"
FB11 "BLM18SG221TN1D" 0603L 3177.13,6025.89 r0 top value="220 ohm"
FB12 "Ferrite_Bead" LI0603D 4361.69,3130.09 r270 top value="300 ohm"
FB13 "Ferrite_Bead" 0603 820.5,1054.09 r90 top value="60 ohm"
FID1 "Fiducial" Fiducial10-20 100,400 r90 top
FID2 "Fiducial" Fiducial10-20 6500,8600 r90 top
FID3 "Fiducial" Fiducial10-20 400,8500 r90 top
FID4 "Fiducial" Fiducial10-20 100,400 r90 bottom
FID5 "Fiducial" Fiducial10-20 6500,8600 r90 bottom
FID6 "Fiducial" Fiducial10-20 400,8500 r90 bottom
H1 "SJ61A6" 3M_SJ61A6 200,200 r180 bottom
H2 "SJ61A6" 3M_SJ61A6 6750,225 r180 bottom
H3 "SJ61A6" 3M_SJ61A6 6770,8917 r180 bottom
H4 "SJ61A6" 3M_SJ61A6 241,8939 r180 bottom
H5 "SJ61A6" 3M_SJ61A6 225,2050 r180 bottom
H6 "SJ61A6" 3M_SJ61A6 6819,2251.4 r180 bottom
J2 "VIN1" FP-CON-SMA-EDGE-S_CONN_JACK-MFG 7182.4,1490 r270 top
J3 "VIN2" FP-CON-SMA-EDGE-S_CONN_JACK-MFG 7182.4,880 r270 top
J4 "IN0_P" FP-CON-SMA-EDGE-S_CONN_JACK-MFG 6247.5,9343.4 r0 top
J5 "IN0_N" FP-CON-SMA-EDGE-S_CONN_JACK-MFG 5747.5,9343.4 r0 top
J6 "IN1_P" FP-CON-SMA-EDGE-S_CONN_JACK-MFG 4747.5,9343.4 r0 top
J7 "IN1_N" FP-CON-SMA-EDGE-S_CONN_JACK-MFG 5247.5,9343.4 r0 top
J8 "142-0701-201" Johnson_142-0701-20x 3479,2967.4 r0 top
J9 "OUT0_P" FP-CON-SMA-EDGE-S_CONN_JACK-MFG -182.4,4112.5 r90 top
J10 "OUT1_P" FP-CON-SMA-EDGE-S_CONN_JACK-MFG -182.4,2612.5 r90 top
J11 "OUT0_N" FP-CON-SMA-EDGE-S_CONN_JACK-MFG -182.4,3612.5 r90 top
J12 "OUT1_N" FP-CON-SMA-EDGE-S_CONN_JACK-MFG -182.4,3112.5 r90 top
J13 "OUT2_P" FP-CON-SMA-EDGE-S_CONN_JACK-MFG 7182.4,2612.5 r270 top
J14 "OUT3_P" FP-CON-SMA-EDGE-S_CONN_JACK-MFG 7182.4,4112.5 r270 top
J15 "OUT2_N" FP-CON-SMA-EDGE-S_CONN_JACK-MFG 7182.4,3112.5 r270 top
J16 "OUT3_N" FP-CON-SMA-EDGE-S_CONN_JACK-MFG 7182.4,3612.5 r270 top
J17 "OUT4_P" FP-CON-SMA-EDGE-S_CONN_JACK-MFG 7182.4,6112.5 r270 top
J18 "OUT5_P" FP-CON-SMA-EDGE-S_CONN_JACK-MFG 7182.4,4612.5 r270 top
J19 "OUT4_N" FP-CON-SMA-EDGE-S_CONN_JACK-MFG 7182.4,5612.5 r270 top
J20 "OUT5_N" FP-CON-SMA-EDGE-S_CONN_JACK-MFG 7182.4,5112.5 r270 top
J21 "OUT6_P" FP-CON-SMA-EDGE-S_CONN_JACK-MFG 7182.4,6612.5 r270 top
J22 "OUT7_P" FP-CON-SMA-EDGE-S_CONN_JACK-MFG 7182.4,8112.5 r270 top
J23 "OUT6_N" FP-CON-SMA-EDGE-S_CONN_JACK-MFG 7182.4,7112.5 r270 top
J24 "OUT7_N" FP-CON-SMA-EDGE-S_CONN_JACK-MFG 7182.4,7612.5 r270 top
J25 "OUT8_P" FP-CON-SMA-EDGE-S_CONN_JACK-MFG 2247.5,9343.4 r0 top
J26 "OUT9_P" FP-CON-SMA-EDGE-S_CONN_JACK-MFG 747.5,9343.4 r0 top
J27 "OUT8_N" FP-CON-SMA-EDGE-S_CONN_JACK-MFG 1747.5,9343.4 r0 top
J28 "OUT9_N" FP-CON-SMA-EDGE-S_CONN_JACK-MFG 1247.5,9343.4 r0 top
J29 "OUT10_P" FP-CON-SMA-EDGE-S_CONN_JACK-MFG -182.4,8112.5 r90 top
J30 "OUT11_P" FP-CON-SMA-EDGE-S_CONN_JACK-MFG -182.4,6612.5 r90 top
J31 "OUT10_N" FP-CON-SMA-EDGE-S_CONN_JACK-MFG -182.4,7612.5 r90 top
J32 "OUT11_N" FP-CON-SMA-EDGE-S_CONN_JACK-MFG -182.4,7112.5 r90 top
J33 "OUT12_P" FP-CON-SMA-EDGE-S_CONN_JACK-MFG -182.4,6112.5 r90 top
J34 "OUT13_P" FP-CON-SMA-EDGE-S_CONN_JACK-MFG -182.4,4612.5 r90 top
J35 "OUT12_N" FP-CON-SMA-EDGE-S_CONN_JACK-MFG -182.4,5612.5 r90 top
J36 "OUT13_N" FP-CON-SMA-EDGE-S_CONN_JACK-MFG -182.4,5112.5 r90 top
J37 "IN2_P" FP-CON-SMA-EDGE-S_CONN_JACK-MFG 4247.5,9343.4 r0 top
J38 "IN3_P" FP-CON-SMA-EDGE-S_CONN_JACK-MFG 2747.5,9343.4 r0 top
J39 "IN2_N" FP-CON-SMA-EDGE-S_CONN_JACK-MFG 3747.5,9343.4 r0 top
J40 "IN3_N" FP-CON-SMA-EDGE-S_CONN_JACK-MFG 3247.5,9343.4 r0 top
J41 "USB" CONN_USB-Mini-B-1734035-2 206,730 r270 top locked
J42 "HTST-115-01-L-DV" Samtec_HTST-115-01-x-DV 1629,1838 r90 bottom
J500 "393570005" Molex_0393570005 5581.7,101.2 r90 top
JP1 "61000621121" Wurth_61000621121 5301.7,978 r180 top
JP2 "61000621121" Wurth_61000621121 5382,1540 r180 top
JP4 "61000621121" Wurth_61000621121 4454,2347.6 r180 top
JP5 "54202-G0807LF" FP-54202-G0807LF_HDR14-MFG 1528.36,1773.4 r0 top
L500 "BLE18PS080SN1" FP-BLE18PS080SN1_0603-MFG 6129.2,1355.2 r270 top
L501 "XGL4030-222MEC" FP-XGL4030-222MEC_SMT_IND_4MM0_4MM0-MFG 6302.4,1736.2 r180 top
L502 "BLE18PS080SN1" FP-BLE18PS080SN1_0603-MFG 5996.4,1424.6 r180 top
L503 "BLE18PS080SN1" FP-BLE18PS080SN1_0603-MFG 5544.9,1947.3 r180 top
LBL1 "THT-14-423-10" Label_650x200 4147,669 r180 top
Logo2 "FCC disclaimer" FCC_disclaimer 2475,1613 r0 top
Logo4 "WEEE logo" WEEE_Minimum 6721.9,327 r0 top
MH1 "MTG_HOLE" MTGP_252mil_157mil_6Via 6349,186 r0 top
NT1 "NT_0603" NetTie_0603 4549.22,1001.42 r0 top net-tie
Q1 "BSS138" SOT-23 2406.08,432.49 r270 top value=50V
Q2 "FDV301N" SOT-23 1905.41,2386.9 r0 top value=25V
Q3 "BSS138" SOT-23 2406.09,1182.82 r270 top value=50V
Q4 "BSS138" SOT-23 2420.31,1918.8 r270 top value=50V
Q5 "BSS138" SOT-23 2238.4,154.32 r90 top value=50V
R1 "CRCW060323K2FKEA" 0603 5991.2,1856.4 r180 bottom value=23.2k
R2 "CRCW060313K3FKEA" 0603 6085.2,1859.4 r90 bottom value=13.3k
R3 "CRCW060323K2FKEA" 0603 6343.2,1784.4 r180 bottom value=23.2k
R5 "CRCW060313K3FKEA" 0603 6406.2,1730.4 r180 bottom value=13.3k
R6 "RK73Z1ETTP" 0402L 3266,5144 r225 top value=0
R7 "RK73Z1ETTP" 0402L 3352,4997 r225 top value=0
R8 "CRCW060323K2FKEA" 0603 4924,2701 r90 bottom value=23.2k
R9 "CRCW060313K3FKEA" 0603 5027,2669 r180 bottom value=13.3k
R10 "RK73Z1ETTP" 0402L 3308,5123 r225 top value=0
R11 "CRCW06030000Z0EA" 0603 3832.36,6649.5 r90 top value=0
R12 "CRCW06030000Z0EA" 0603 2816.76,4822.22 r225 top value=0
R13 "Resistor" 0603 4453.36,1983.18 r0 top value=470
R14 "Resistor" 0603 4453.36,1908.44 r0 top value=470
R15 "Resistor" 0603 4331.09,2780.89 r0 top value=470
R16 "CRCW06030000Z0EA" 0603 3693.18,6558.4 r90 top value=0
R17 "CRCW06030000Z0EA" 0603 3301.03,4423.17 r270 top value=0
R18 "CRCW06030000Z0EA" 0603 3511.08,6279.33 r90 top value=0
R19 "CRCW06030000Z0EA" 0603 4947.24,5478.79 r0 top value=0
R20 "CRCW06030000Z0EA" 0603 3612.65,4530.27 r270 top value=0
R21 "CRCW06030000Z0EA" 0603 2636.5,5573.42 r180 top value=0
R22 "CRCW06030000Z0EA" 0603 4304.83,5210.12 r0 top value=0
R24 "CRCW06030000Z0EA" 0603 3300,6380 r180 top value=0
R25 "CRCW06030000Z0EA" 0603 3160.02,6175.71 r90 top value=0
R26 "CRCW04020000Z0EDHP" 0402L 3934.69,5937.26 r225 top value=0
R27 "CRCW04020000Z0EDHP" 0402L 3778.3,5777.55 r225 top value=0
R28 "RC0402JR-0751RL" 0402S 3895.63,5872.08 r135 top value=51
R29 "CRCW0603100RFKEA" 0603S 3828.19,5873.76 r315 top value=100
R30 "CRCW04020000Z0EDHP" 0402L 3891.24,5977.73 r225 top value=0
R31 "CRCW04020000Z0EDHP" 0402L 3732.94,5822.69 r225 top value=0
R32 "RC0402JR-0751RL" 0402S 3827.19,5939.76 r315 top value=51
R33 "CRCW04020000Z0EDHP" 0402L 3743.11,6068.89 r225 top value=0
R34 "CRCW04020000Z0EDHP" 0402L 3607.91,5932.81 r225 top value=0
R35 "RC0402JR-0751RL" 0402S 3679.67,6030.76 r315 top value=51
R36 "CRCW0603100RFKEA" 0603S 3679.61,5962.39 r135 top value=100
R37 "CRCW04020000Z0EDHP" 0402L 3787.11,6026.89 r225 top value=0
